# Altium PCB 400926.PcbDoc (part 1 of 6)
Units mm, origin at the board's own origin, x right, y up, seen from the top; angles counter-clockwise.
Board outline 148.5 x 63.5 mm, 4 copper layers (Top Layer, Mid-Layer 1, Mid-Layer 2, Bottom Layer), stack 1.514 mm thick; 311 components, 281 nets, 1495 pads, 2232 vias.
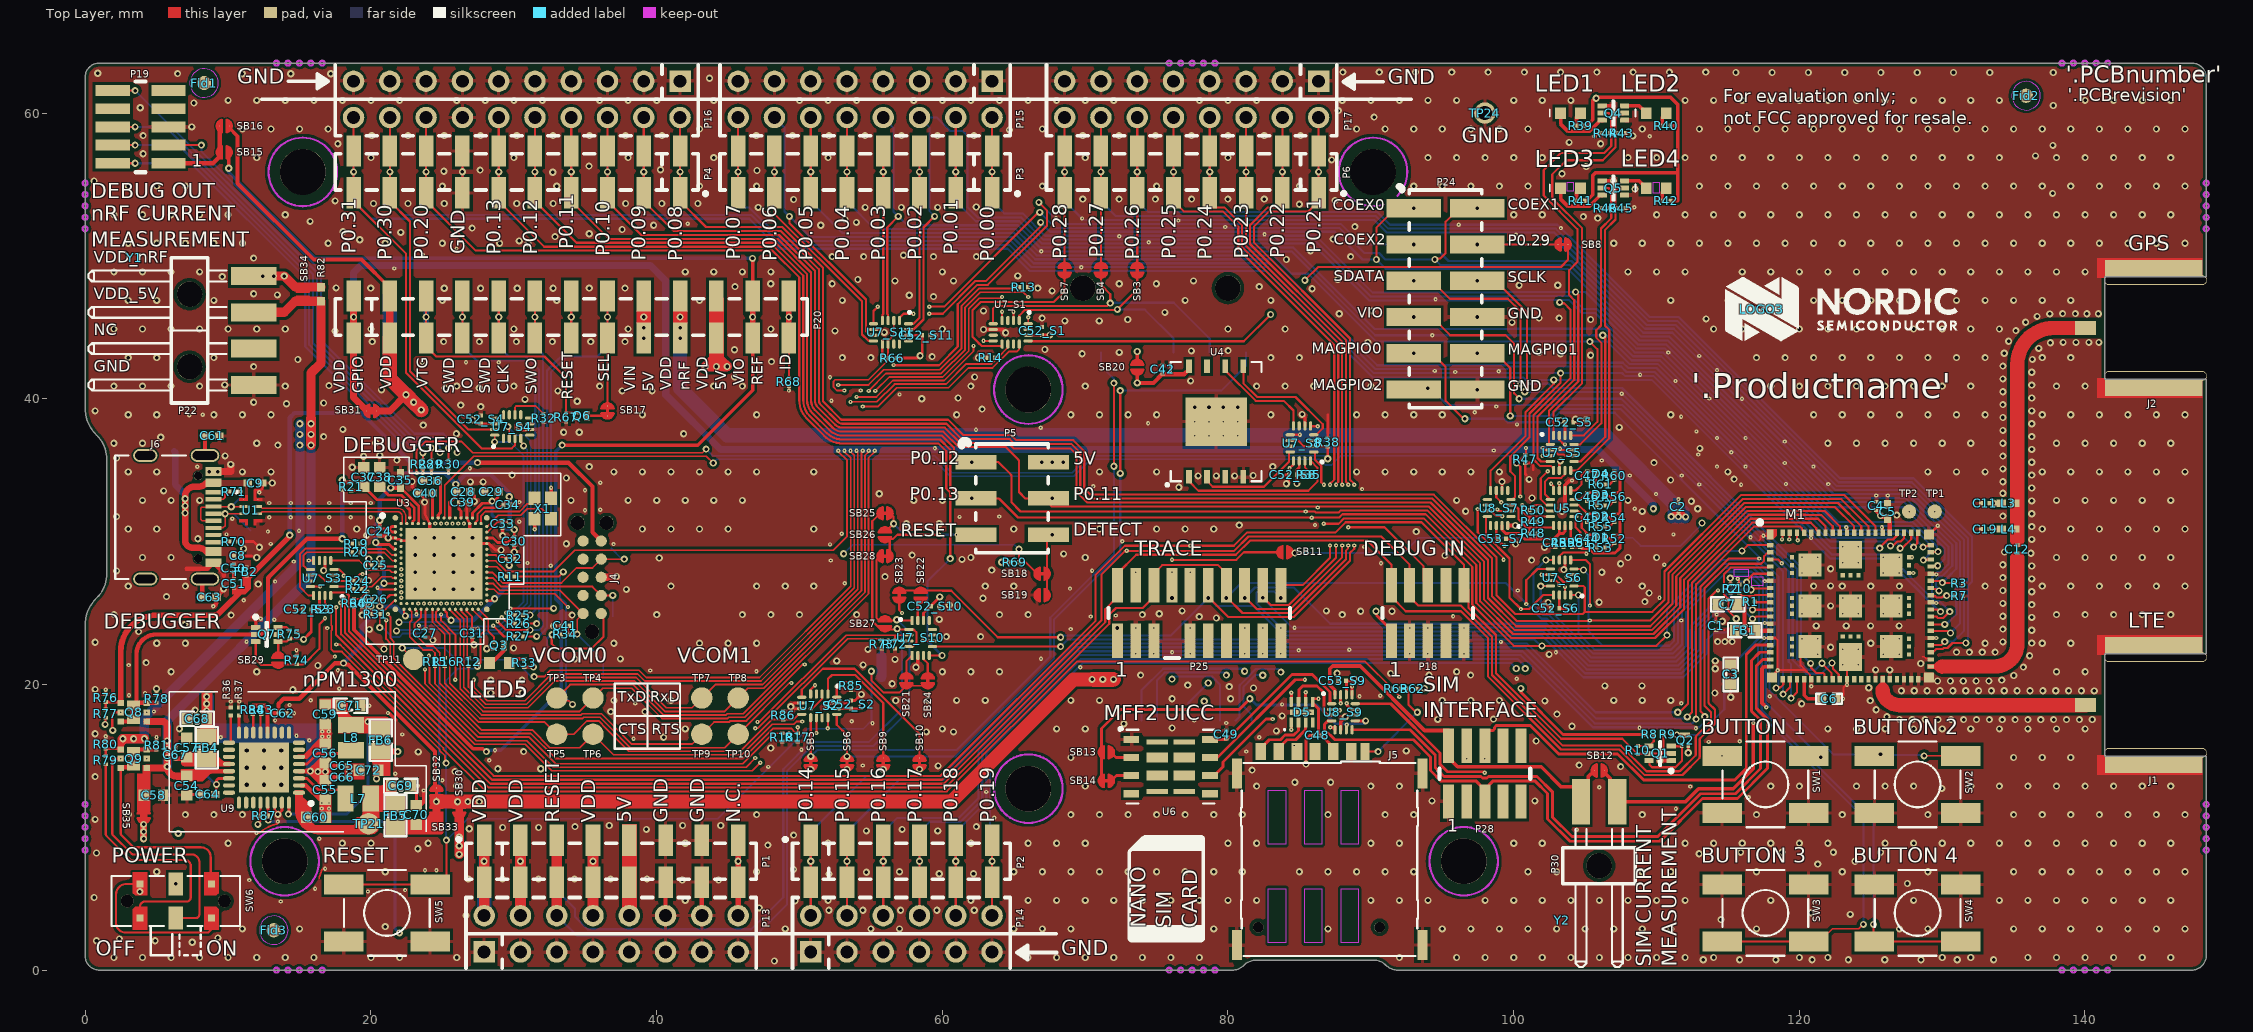
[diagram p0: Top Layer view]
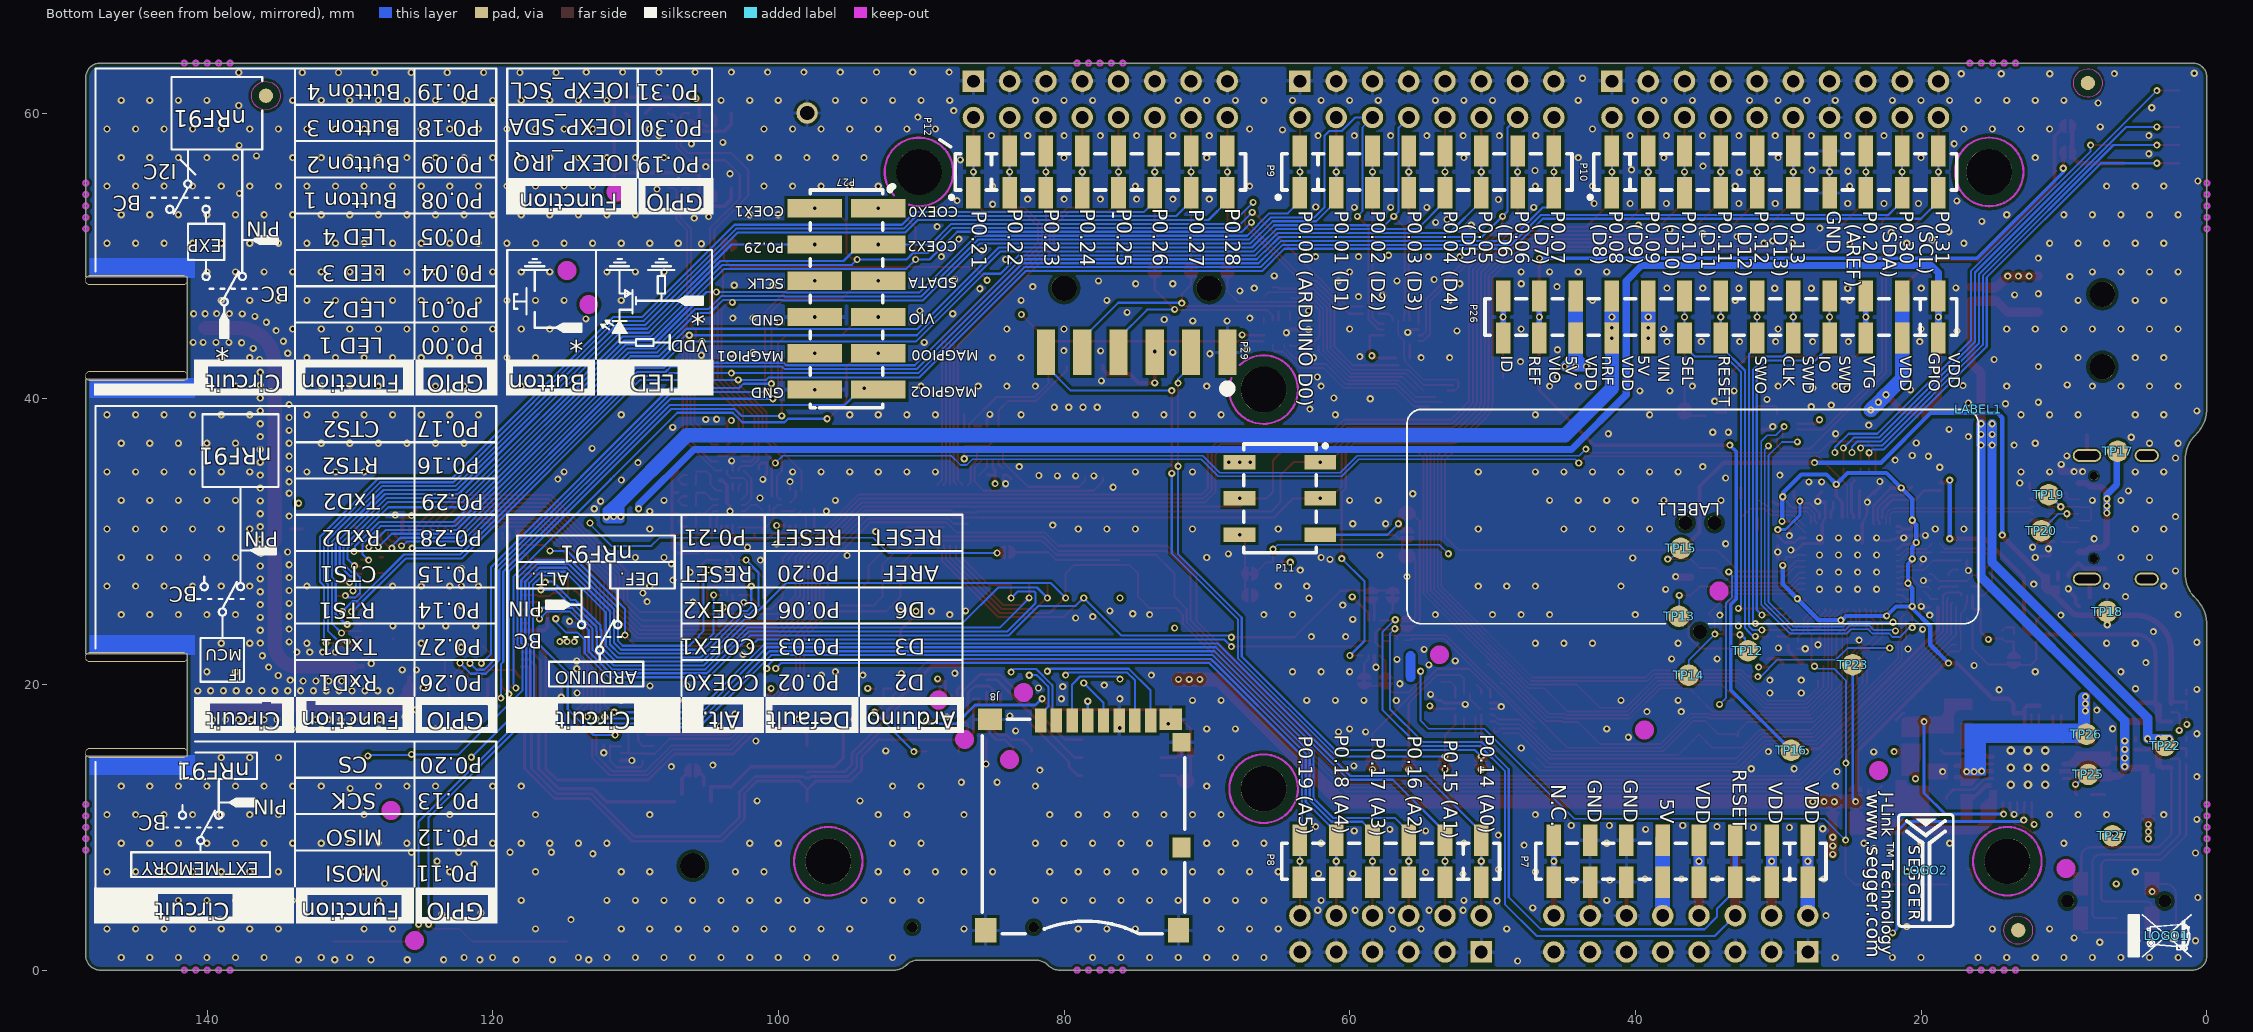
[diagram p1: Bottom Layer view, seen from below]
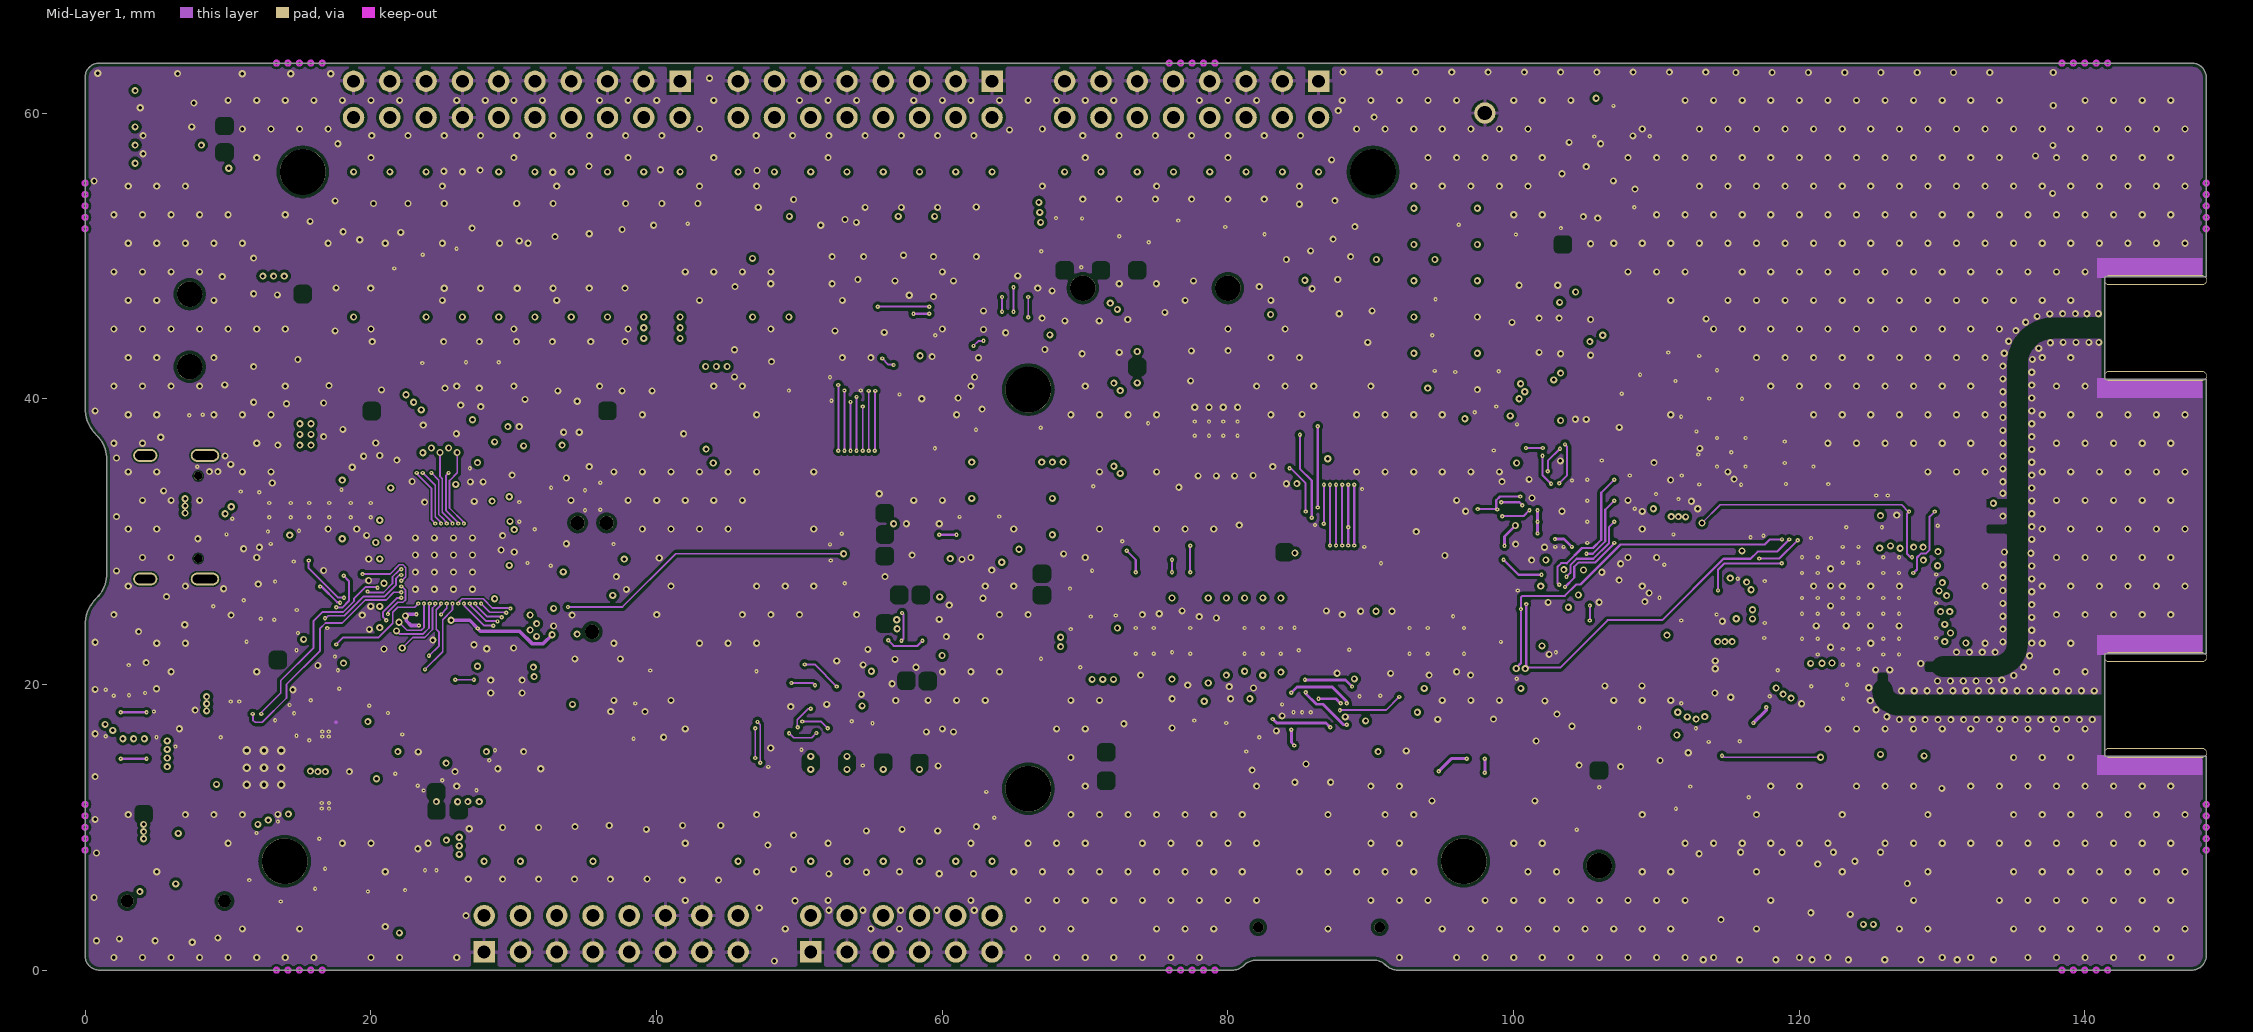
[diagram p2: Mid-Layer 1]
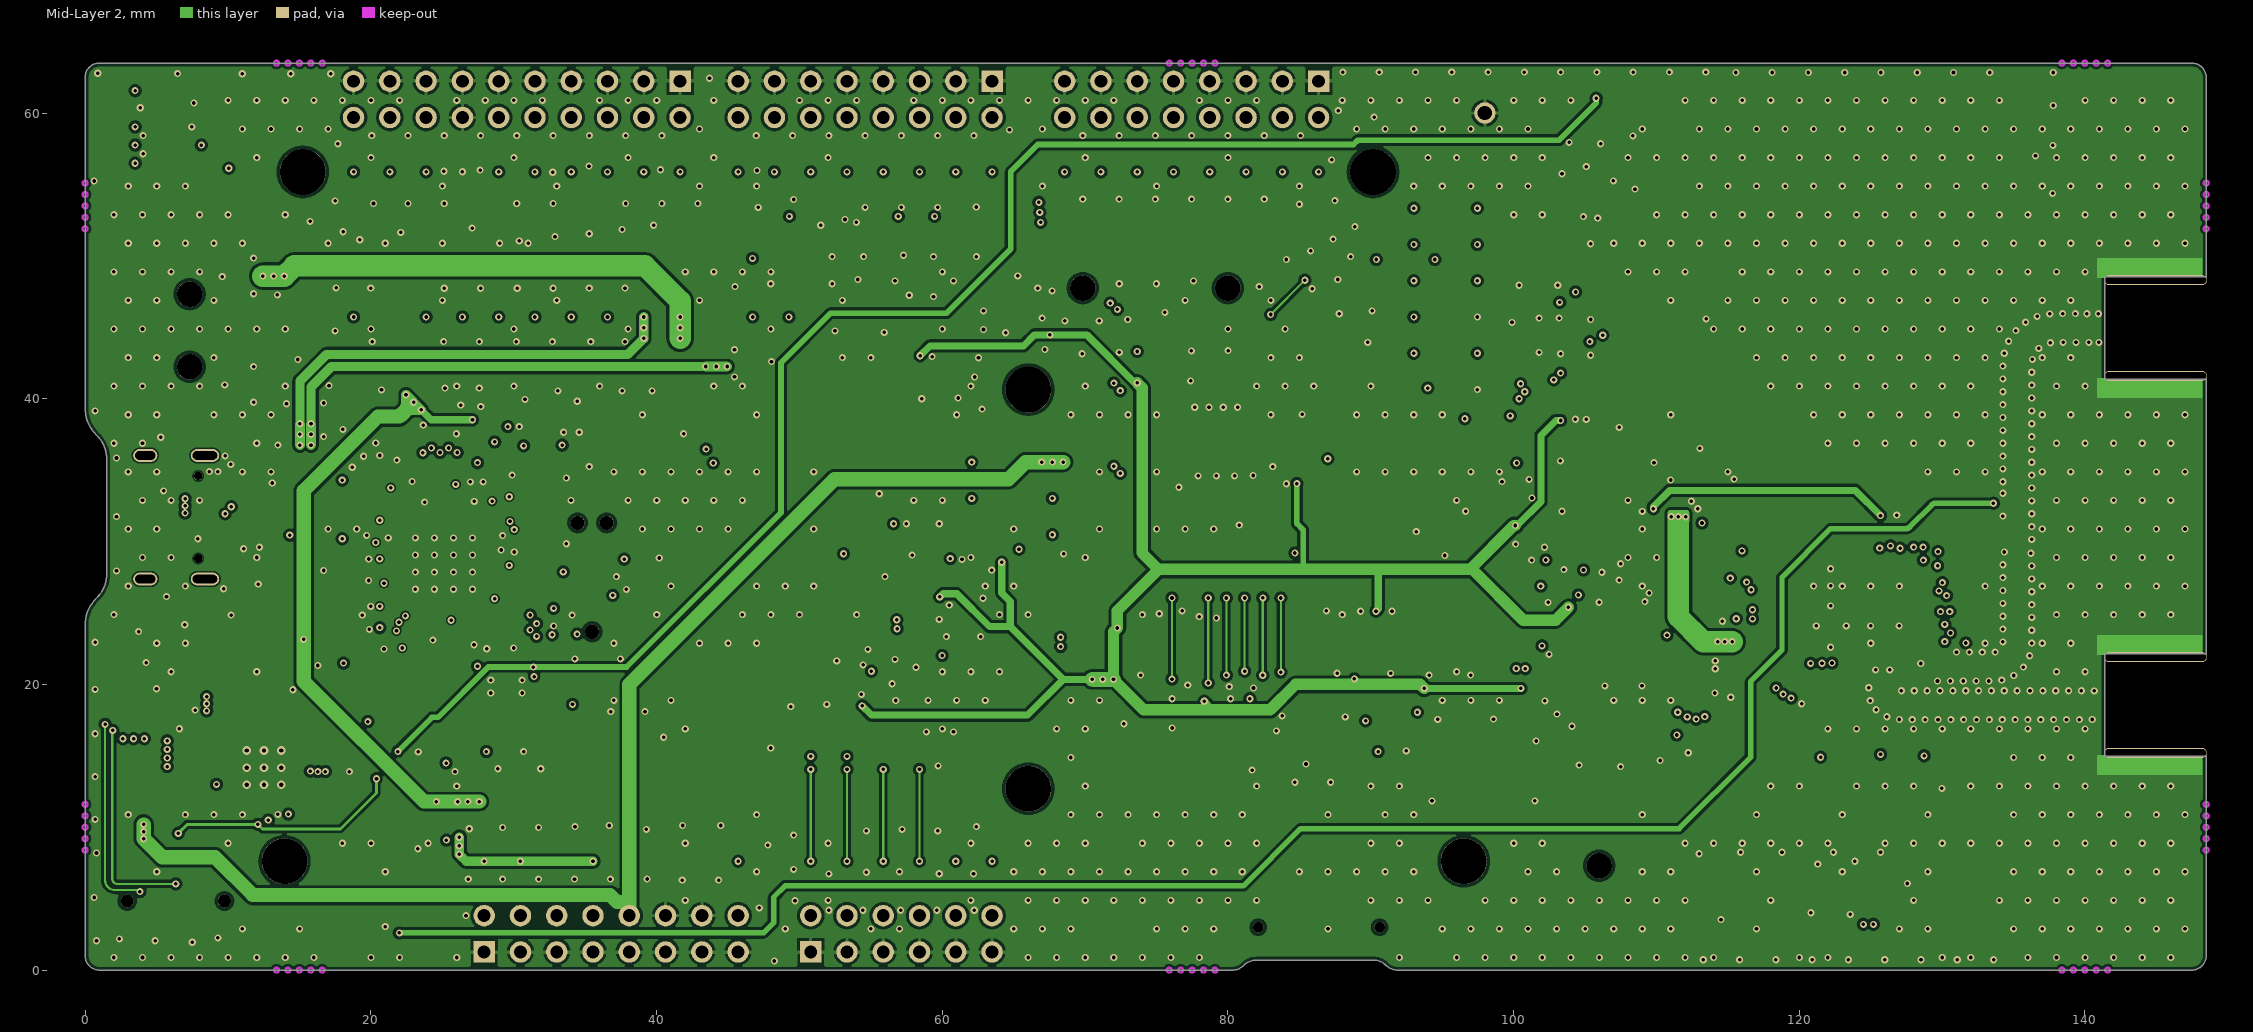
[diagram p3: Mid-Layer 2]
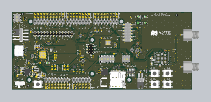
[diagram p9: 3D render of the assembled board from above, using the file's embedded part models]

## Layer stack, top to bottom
Top Solder: solder mask 0.05, Solder Resist Halogen-Free, Dk 3.5
Top Layer: signal copper 0.035
Dielectric1: prepreg 0.072, FR-4 Halogen-Free, Dk 4.18
Mid-Layer 1: signal copper 0.035
Dielectric2: core 1.23, FR-4 Halogen-Free, Dk 4.74
Mid-Layer 2: signal copper 0.035
Dielectric3: prepreg 0.072, FR-4 Halogen-Free, Dk 4.18
Bottom Layer: signal copper 0.035
Bottom Solder: solder mask 0.05, Solder Resist Halogen-Free, Dk 3.5

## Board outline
1,-0.001 cw(c1,0.999) 0,0.999 0,24.12 cw(c2.716,24.12) 0.796,26.041 0.962,26.207 ccw(c-0.876,27.75) 1.524,27.75 1.524,35.75 ccw(c-0.876,35.75) 0.962,37.293 0.796,37.459 cw(c2.716,39.38) 0,39.38 0,62.499 cw(c1,62.499) 1,63.499 147.5,63.499 cw(c147.5,62.499) 148.5,62.499 148.5,48.549 141.4,48.549 141.4,41.349 148.5,41.349 148.5,22.156 141.4,22.156 141.4,14.956 148.5,14.956 148.5,0.999 cw(c147.5,0.999) 147.5,-0.001 91.9,-0.001 cw(c91.9,1.179) 91.066,0.345 ccw(c90.231,-0.49) 90.231,0.69 81.969,0.69 ccw(c81.969,-0.49) 81.134,0.345 cw(c80.3,1.179) 80.3,-0.001

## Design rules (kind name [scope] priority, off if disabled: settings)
BoardOutlineClearance BoardOutlineClearance_SMA [HasFootprint('CONSMA024-G')] p1: gap=0 ignorepadtopadclearanceinfootprint=FALSE
BoardOutlineClearance [OnLayer('Top Layer') or OnLayer('Bottom Layer') or OnLayer('Mid-Layer 1') or OnLayer('Mid-Layer 2')] p2: gap=0.244 ignorepadtopadclearanceinfootprint=FALSE
Clearance SMA [HasFootprint('CONSMA024-G')] p1: gap=0 ignorepadtopadclearanceinfootprint=FALSE
Clearance USB_C [InComponent('J6')] p2: gap=0.1 ignorepadtopadclearanceinfootprint=FALSE
Clearance IMCU_room [WithinRoom('IMCU')] p3: gap=0.1 ignorepadtopadclearanceinfootprint=FALSE
Clearance USB_Poly_Clearance [(InNamedPolygon('Top_Layer-GND')) vs (IsTrack or IsArc) and (InDifferentialPair('D') or InDifferentialPair('USB0'))] p4 off: gap=1 ignorepadtopadclearanceinfootprint=FALSE
Clearance "NPTH clearance" [Not PadIsPlated And HoleSize > 0] p5: gap=0.23 ignorepadtopadclearanceinfootprint=FALSE
Clearance SB_Clearance [HasFootprint('Solderbridge') or HasFootprint('QFN40P180X140X55-10N')] p6: gap=0.127 ignorepadtopadclearanceinfootprint=FALSE except(0: Arc-Hole Track-Hole SMDPad-Hole THPad-Hole Via-Hole Fill-Hole Poly-Hole Region-Hole Text-Hole)
Clearance CSP_Clearance [HasFootprint('BGA4C40P2X2_76X76X62')] p7: gap=0.127 ignorepadtopadclearanceinfootprint=FALSE except(0: Arc-Hole Track-Hole SMDPad-Hole THPad-Hole Via-Hole Fill-Hole Poly-Hole Region-Hole Text-Hole)
Clearance P23_Clearance [HasFootprint('FPC_05P-0.5mm-RA-SMD')] p8: gap=0.127 ignorepadtopadclearanceinfootprint=FALSE except(0: Arc-Hole Track-Hole SMDPad-Hole THPad-Hole Via-Hole Fill-Hole Poly-Hole Region-Hole Text-Hole)
Clearance PSON35P100X50-8N_Clearance [HasFootprint('PSON35P100X50-8N')] p9: gap=0.15 ignorepadtopadclearanceinfootprint=FALSE except(0: Arc-Hole Track-Hole SMDPad-Hole THPad-Hole Via-Hole Fill-Hole Poly-Hole Region-Hole Text-Hole)
Clearance "Net tie_clearance" [InComponent('NT*') vs IsPad] p10: gap=0.001 ignorepadtopadclearanceinfootprint=TRUE
Clearance Polygon_Clearance [InNamedPolygon('Top_Layer-GND') or InNamedPolygon('Bottom_Layer-GND') or InNamedPolygon('Mid_Layer_1-GND') or InNamedPolygon('Mid_Layer_2-GND')] p11: gap=0.2 ignorepadtopadclearanceinfootprint=FALSE
Clearance Top_layer_Clearance [All vs OnLayer('Top Layer')] p12: gap=0.125 ignorepadtopadclearanceinfootprint=FALSE
Clearance USB_Clearance [InDifferentialPairClass('All Differential Pairs')] p13: gap=0.15 ignorepadtopadclearanceinfootprint=FALSE
Clearance RF_Clerance [InNet('RF') or InNet('ANT')] p14: gap=0.203 ignorepadtopadclearanceinfootprint=FALSE except(0: Arc-Hole Track-Hole SMDPad-Hole THPad-Hole Via-Hole Fill-Hole Poly-Hole Region-Hole Text-Hole)
Clearance [All] p15: gap=0.125 ignorepadtopadclearanceinfootprint=FALSE except(0: Poly-Region Region-Region)
ComponentClearance [All] p1 off: gap=0.254 collisioncheckmode=3 verticalgap=0.254 showdistances=FALSE
DiffPairsRouting [InDifferentialPairClass('All Differential Pairs')] p1: maxlimit=0.15 minlimit=0.127 mostfreqgap=0.15 toplayer_mingap=0.15 toplayer_minwidth=0.1 toplayer_maxwidth=0.1 toplayer_prefwidth=0.1 midlayer1_maxgap=0.127 midlayer1_prefgap=0.127 midlayer1_minwidth=0.054 midlayer1_maxwidth=0.054 midlayer1_prefwidth=0.054 midlayer2_maxgap=0.127 midlayer2_prefgap=0.127 midlayer2_minwidth=0.054 midlayer2_maxwidth=0.054 midlayer2_prefwidth=0.054 bottomlayer_mingap=0.15 bottomlayer_minwidth=0.1 bottomlayer_maxwidth=0.1 bottomlayer_prefwidth=0.1 impedanceprofiledriven=TRUE impedanceprofileid={5F1D737F-A6A0-4321-8E3C-81C77A155CAF} impedanceprofilevalue=90.000000 maxuncoupledlength=12.7
FabricationTestPointUsage TestPointUsage [All] p1: valid=0 allowmultiple=FALSE
FabricationTestpoint Testpoint [All] p1: side=3 testpointundercomponent=TRUE minsize=1.016 maxsize=2.54 preferedsize=1.524 minholesize=0 maxholesize=1.016 preferedholesize=0.813 testpointgrid=0.025 allowsidetop=TRUE allowsidebottom=TRUE usegrid=TRUE gridtolerance=0
Height [All] p1 off: minheight=0 maxheight=25.4 prefheight=12.7
HoleSize [All] p1: absolutevalues=TRUE maxlimit=10 minlimit=0.1 maxpercent=80.000 minpercent=20.000
HoleToHoleClearance [All] p1: gap=0.25 allowstackedmicrovias=FALSE
MaxMinImpedance [InNetClass('USB')] p1: minimum=81.00 maximum=99.00
MinimumAnnularRing [All] p1 off: minimumring=0.152
MinimumSolderMaskSliver USB-C [HasFootprint('SD-80259-001')] p1: minsoldermaskwidth=0
MinimumSolderMaskSliver PMIC [WithinRoom('nPM1300')] p2: minsoldermaskwidth=0
MinimumSolderMaskSliver [All] p3: minsoldermaskwidth=0.05
NetAntennae NetAntennae_ANT [InNet('ANT')] p1: netantennaetolerance=40
NetAntennae [All] p2: netantennaetolerance=0
PlaneClearance [All] p1: clearance=0.25
PlaneConnect [All] p1: planeconnectstyle=Direct reliefexpansion=0.508 reliefentries=4 reliefconductorwidth=0.254 reliefairgap=0.254
PolygonConnect VDD_nRF [InNet('VDD_nRF')] p1: connectstyle=Direct reliefconductorwidth=0.254 reliefentries=4 polygonreliefangle="90 Angle" airgapwidth=0.254
PolygonConnect VCC_and_VDD [InNet('NetC50_2') or InNet('NetC8_2') or InNet('NetC70_2') or InNet('VDD')] p2: connectstyle=Direct reliefconductorwidth=0.254 reliefentries=4 polygonreliefangle="90 Angle" airgapwidth=0.254
PolygonConnect GND_Poly [isVia and innet(gnd) or isVia and innet('VDD') or HasFootprint('COAXIAL-SWF') or isVia and innet('VDD_SAM') or InComponent('R80') or HasFootprint('COAXIAL RF U.FL-R-SMT-1') or HasFootprint('DSGP.1575.18') or HasFootprint('DX07S016JA1R1500') or InComponent('C65')or InComponent('C66')or InComponent('C72')] p3: connectstyle=Direct reliefconductorwidth=0.254 reliefentries=4 polygonreliefangle="90 Angle" airgapwidth=0.254
PolygonConnect General [All] p4: connectstyle=Relief reliefconductorwidth=0.25 reliefentries=4 polygonreliefangle="90 Angle" airgapwidth=0.2
RoomDefinition IMCU [InComponentClass('IMCU') vs False] p1: confinementstyle=ConfineIn formatcopy=TRUE lockcomponents=FALSE outline 18.088,33.042 18.088,34.655 18.67,34.655 18.67,36.018 21.455,36.018 21.455,35.513 22.755,35.513 22.755,34.943 25.405,34.943 25.405,34.163 27.705,34.163 29.68,34.163 29.68,33.843 33.38,33.843 33.38,30.782 30.586,30.782 30.586,29.226 30.581,29.226 30.581,28.246 28.954,28.246 28.954,24.429 27.636,24.429 27.636,22.776 24.279,22.776 24.279,20.47 21.721,20.47 21.721,24.429 20.321,24.429 20.321,25.421 19.543,25.421 19.543,27.797 19.543,33.008 18.67,33.008 18.67,33.042
RoomDefinition nPM1300 [InComponentClass('nPM1300') vs False] p2: confinementstyle=ConfineIn formatcopy=TRUE lockcomponents=FALSE outline 5.35,8.144 5.35,10.652 5.818,10.652 5.818,15.86 6.348,15.86 6.348,17.025 6.398,17.025 6.398,18.375 9.691,18.375 9.691,18.878 10.26,18.878 10.26,18.885 16.048,18.885 16.048,19.362 17.248,19.362 17.248,19.375 19.114,19.375 19.114,39.996 21.021,39.996 21.021,22.633 26.049,22.633 26.049,12.151 27.049,12.151 27.049,10.244 23.973,10.244 23.973,9.419 22.781,9.419 22.781,9.117 20.381,9.117 20.381,8.542 7.858,8.542 7.858,8.144
RoutingLayers RoutingLayers_1 [IsMicroVia] p1: top layer_v5=TRUE mid layer 1_v5=TRUE mid layer 2_v5=FALSE bottom layer_v5=FALSE
RoutingLayers [All] p2: top layer_v5=TRUE mid layer 1_v5=TRUE mid layer 2_v5=TRUE bottom layer_v5=TRUE
RoutingVias [All] p1: holewidth=0.25 width=0.5 viastyle="Through Hole" minholewidth=0.1 minwidth=0.3 maxholewidth=0.305 maxwidth=0.61
ShortCircuit "PVSS and GND" [InNet('PVSS1') or InNet('PVSS2') vs InNet('GND')] p1: allowed=TRUE
ShortCircuit ShortCircuit_1 [HasFootprint('P822601')] p2: allowed=TRUE
ShortCircuit [All] p3: allowed=FALSE
SilkToSilkClearance [All] p1: silktosilkclearance=0.15
SilkToSolderMaskClearance SilkscreenOverComponentPads [IsPad] p1: minsilkscreentomaskgap=0.254 clearancetoexposedcopper=TRUE
SolderMaskExpansion SolderMaskExpansion_Via [IsVia] p1: expansion=0.102 istentingtop=TRUE
SolderMaskExpansion SolderMaskExpansion_USB [HasFootprint('L-KLS1-5473')] p2: expansion=0.06 istentingtop=FALSE
SolderMaskExpansion [All] p3: expansion=0.076 istentingtop=FALSE
SupplyNets "Schematic Supply Nets_19" [InNet('VDD_1V8')] p1: voltage=0.000
SupplyNets "Schematic Supply Nets_18" [InNet('VBUSOUT')] p2: voltage=0.000
SupplyNets "Schematic Supply Nets_17" [InNet('VDD')] p3: voltage=0.000
SupplyNets "Schematic Supply Nets_16" [InNet('VBUS')] p4: voltage=0.000
SupplyNets "Schematic Supply Nets_15" [InNet('VIN')] p5: voltage=0.000
SupplyNets "Schematic Supply Nets_14" [InNet('GND')] p6: voltage=0.000
SupplyNets "Schematic Supply Nets_13" [InNet('VIOEXT')] p7: voltage=0.000
SupplyNets "Schematic Supply Nets_12" [InNet('5V')] p8: voltage=0.000
SupplyNets "Schematic Supply Nets_11" [InNet('VIO_REF')] p9: voltage=0.000
SupplyNets "Schematic Supply Nets_10" [InNet('VIN_5V')] p10: voltage=0.000
SupplyNets "Schematic Supply Nets_9" [InNet('VDD_IMCU')] p11: voltage=0.000
SupplyNets "Schematic Supply Nets_8" [InNet('VIO')] p12: voltage=0.000
SupplyNets "Schematic Supply Nets_7" [InNet('VDD_3V0')] p13: voltage=0.000
SupplyNets "Schematic Supply Nets_6" [InNet('VIN:5V')] p14: voltage=0.000
SupplyNets "Schematic Supply Nets_5" [InNet('FB2:VBUS')] p15: voltage=0.000
SupplyNets "Schematic Supply Nets_4" [InNet('VDD_nRF')] p16: voltage=0.000
SupplyNets "Schematic Supply Nets_3" [InNet('VDD_GNSS')] p17: voltage=0.000
SupplyNets "Schematic Supply Nets_2" [InNet('VDD_5V')] p18: voltage=0.000
SupplyNets "Schematic Supply Nets_1" [InNet('VSYS')] p19: voltage=0.000
SupplyNets "Schematic Supply Nets" [InNet('VDD_GPIO')] p20: voltage=0.000
UnpouredPolygon [All] p1 off:
Width Width_RF [InNet('ANT') or InNet('LTE_RF1') or InNet('GPS_RF1')] p1: maxlimit=1.008 minlimit=0.1 preferedwidth=1.008 toplayer_minwidth=1 bottomlayer_minwidth=1 impedanceprofiledriven=TRUE impedanceprofileid={28F3A609-7DB3-45B1-BB45-39A827C1017D} impedanceprofilevalue=50.000000 minimp=50.000000 maximp=50.000000 favimp=50.000000
Width Width_Diff [(InDifferentialPairClass('All Differential Pairs'))] p2: maxlimit=0.165 minlimit=0.1 preferedwidth=0.165 toplayer_maxwidth=0.1 toplayer_prefwidth=0.1 bottomlayer_maxwidth=0.1 bottomlayer_prefwidth=0.1 minimp=50.000000 maximp=50.000000 favimp=50.000000
Width Width_GPIO [InNetClass('GPIO')] p3: maxlimit=0.152 minlimit=0.125 preferedwidth=0.15 minimp=50.000000 maximp=50.000000 favimp=50.000000
Width Width_GPIO_1 [InNetClass('COEX')] p4: maxlimit=0.152 minlimit=0.125 preferedwidth=0.15 minimp=50.000000 maximp=50.000000 favimp=50.000000
Width Width_GPIO_2 [InNetClass('SWD')] p5: maxlimit=0.152 minlimit=0.125 preferedwidth=0.15 minimp=50.000000 maximp=50.000000 favimp=50.000000
Width Width_GPIO_3 [InNetClass('UART')] p6: maxlimit=0.152 minlimit=0.125 preferedwidth=0.15 minimp=50.000000 maximp=50.000000 favimp=50.000000
Width [All] p7: maxlimit=2.54 minlimit=0.125 preferedwidth=0.15
14 further rules are at their usual default settings.

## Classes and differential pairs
channel class pca10201_switch_nx: S7 S9
channel class pca10201_switch_fsa: S1 S2 S3 S4 S5 S6 S8 S10 S11
differential pair class IMCU: D
differential pair class D:J6: D:J6
net class USB: D:J6_N D:J6_P D_N D_P
net class VCOM: VCOM0_CTRL VCOM0_CTS VCOM0_HWFC VCOM0_RTS VCOM0_RXD VCOM0_TXD VCOM1_CTRL VCOM1_CTS VCOM1_HWFC VCOM1_RTS VCOM1_RXD VCOM1_TXD
net class nRF9151_UART: P0.14/AIN1 P0.15/AIN2 P0.16/AIN3 P0.17/AIN4 P0.26 P0.27 P0.28 P0.29
net class EXT_MEM: P0.11 P0.12 P0.13/AIN0 P0.20/AIN7
component class IMCU: C24 C25 C26 C27 C28 C29 C30 C31 C32 C33 C34 C35 C36 C37 C38 C39 C40 R21 TP11 U3 X1
component class nPM1300: C54 C55 C56 C57 C59 C60 C62 C64 C65 C66 C67 C68 C69 C70 C71 C72 FB4 FB5 FB6 L7 L8 R36 R37 R87 SB30 SB31 SB32 SB33 TP21 TP23 TP25 TP26 TP27 U9
net class RF: GPS_RF1 GPS_RF2 LTE_RF1
net class SWD: P0.22 RESET SWD0_CLK SWD0_IO SWD0_RESET SWD0_SEL SWD0_SWO SWD1_CLK SWD1_IO SWD1_RESET SWD1_SEL SWD1_SWO SWD3_CLK SWD3_IO SWD3_RESET SWD3_SWO SWD_CTRL SWDCLK SWDIO
net class COEX: COEX0 COEX1 COEX2 MAGPIO0 MAGPIO1 MAGPIO2 MIPI_SCLK MIPI_SDATA MIPI_VIO
net class GPIO: AREF BTN1_EXT BTN2_EXT BTN3_EXT BTN4_EXT BUTTON1 BUTTON2 BUTTON3 BUTTON4 COEX0 COEX1 COEX2 COEX_SELECT COM.CH1_S1 COM.CH2_S2 COM.CH3_S1 COM.CH4_S2 EXT_MEM_C\S\ EXT_MEM_CTRL EXT_MEM_MISO EXT_MEM_MOSI EXT_MEM_SCK IMCU_LED IMCU_SCL IMCU_SDA INT_EXT IOEXP_CTRL LED1 LED1_EXT LED2 LED2_EXT LED3 LED3_EXT LED4 LED4_EXT MAGPIO0 MAGPIO1 MAGPIO2 MIPI_SCLK MIPI_SDATA MIPI_VIO NC.CH1_S3 NC.CH3_S3 NC.CH4_S3 NetC44_1 NetC45_2 NetC46_2 NetC47_2 NetR51_1 NetR58_1 NO.CH1_S8 P0.00 P0.01 P0.02 P0.03 P0.04 P0.05 P0.06 P0.07 P0.08 P0.09 P0.10 P0.11 P0.12 P0.13/AIN0 P0.14/AIN1 P0.15/AIN2 P0.16/AIN3 P0.17/AIN4 P0.18/AIN5 P0.19/AIN6 P0.20/AIN7 P0.21 P0.22 P0.23 P0.24 P0.25 P0.26 P0.27 P0.28 P0.29 P0.30 P0.31 RESET RESET_BUTTON RESET_IN_CTRL RESET_OUT_CTRL SCL_EXT SDA_EXT SHIELD_DETECT SIM_SELECT SWD0_CLK SWD0_IO SWD0_RESET SWD0_SEL SWD0_SWO SWD1_CLK SWD1_IO SWD1_RESET SWD1_SEL SWD1_SWO SWD3_CLK SWD3_IO SWD3_RESET SWD3_SWO SWD_CTRL SWDCLK SWDIO TGT_SCL TGT_SDA TGT_TWI_CTRL UART1.CTS UART1.RTS UART1.RXD UART1.TXD UART2.CTS UART2.RTS UART2.RXD UART2.TXD USB_DETECT VCOM0_CTRL VCOM0_CTS VCOM0_HWFC VCOM0_RTS VCOM0_RXD VCOM0_TXD VCOM1_CTRL VCOM1_CTS VCOM1_HWFC VCOM1_RTS VCOM1_RXD VCOM1_TXD VIO_REF_SENSE
differential pair D: +D_P -D_N
differential pair D:J6: +D:J6_P -D:J6_N

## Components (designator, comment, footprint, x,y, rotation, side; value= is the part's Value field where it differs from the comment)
C1 "1.0µF" CAPC0603X03L_C 114.19,24.099 r90 top
C2 "1.0µF" CAPC0603X03L_C 111.55,32.424 r90 top
C3 "10µF" CAPC1608X06L 115.2,20.699 r270 top
C4 "100nF" CAPC0603X03L_C 125.4,32.499 r90 top
C5 "4.7µF" CAPC1005X04L 126.2,32.099 r90 top
C6 "4.7µF" CAPC1005X04L 122.1,18.999 r0 top
C7 "10µF" CAPC1608X06L 115,25.599 r180 top
C8 "100nF" CAPC0603X03L_C 10.7,28.999 r180 top
C9 "1.0µF" CAPC1005X04L 11.9,34.099 r180 top
C10 "100nF" CAPC0603X03L_C 115.8,26.699 r90 top
C11 "39pF" CAPC0603X03L_C 133.03,32.679 r0 top
C12 "39pF" CAPC0603X03L_C 135.28,29.479 r270 top
C19 "N.C." CAPC0603X03L_C_NC 133.03,30.879 r0 top
C24 "100nF" CAPC0603X03L_C 20.625,30.708 r90 top
C25 "100nF" CAPC0603X03L_C 20.35,28.333 r0 top
C26 "100nF" CAPC0603X03L_C 20.35,25.958 r180 top
C27 "100nF" CAPC0603X03L_C 23.827,23.583 r90 top
C28 "1.0µF" CAPC1005X04L 26.475,33.483 r0 top
C29 "1.0µF" CAPC1005X04L 28.45,33.483 r0 top
C30 "2.2nF" CAPC0603X03L_C 30.05,30.033 r270 top
C31 "100nF" CAPC0603X03L_C 27.1,23.583 r90 top
C32 "100nF" CAPC0603X03L_C 29.775,28.783 r180 top
C33 "100nF" CAPC0603X03L_C 29.225,31.233 r90 top
C34 "100nF" CAPC0603X03L_C 29.575,32.574 r0 top
C35 "1.0µF" CAPC1005X04L 22.075,34.283 r270 top
C36 "1.0µF" CAPC1005X04L 24.175,34.263 r0 top
C37 "4.7µF" CAPC1608X06L 19.5,34.513 r90 top
C38 "4.7µF" CAPC1608X06L 20.625,34.513 r90 top
C39 "100nF" CAPC0603X03L_C 26.444,32.758 r0 top
C40 "1.0µF" CAPC1005X04L 23.825,33.388 r0 top
C41 "10nF" CAPC0603X03L_C 33.625,24.099 r0 top
C42 "100nF" CAPC0603X03L_C 75.45,42.049 r270 top
C43 "100nF" CAPC0603X03L_C 102.927,29.911 r90 top
C44 "1.0µF" CAPC0603X03L_C 105.174,30.19 r270 top
C45 "1.0µF" CAPC0603X03L_C 105.174,31.663 r90 top
C46 "1.0µF" CAPC0603X03L_C 105.174,33.136 r90 top
C47 "1.0µF" CAPC0603X03L_C 105.174,34.61 r90 top
C48 "10nF" CAPC0603X03L_C 86.275,16.424 r180 top
C49 "N.C." CAPC0603X03L_C_NC 79.9,16.499 r270 top
C50 "10nF" CAPC0603X03L_C 10.425,28.149 r90 top
C51 "100nF" CAPC0603X03L_C 10.425,27.049 r270 top
C52_S1 "100nF" CAPC0603X03L_C 67,44.749 r90 top (schematic designator C52)
C52_S2 "100nF" CAPC0603X03L_C 53.625,18.599 r90 top (schematic designator C52)
C52_S3 "100nF" CAPC0603X03L_C 15.55,25.249 r180 top (schematic designator C52)
C52_S4 "100nF" CAPC0603X03L_C 27.7,38.549 r90 top (schematic designator C52)
C52_S5 "100nF" CAPC0603X03L_C 103.898,38.358 r0 top (schematic designator C52)
C52_S6 "100nF" CAPC0603X03L_C 102.923,25.333 r180 top (schematic designator C52)
C52_S8 "100nF" CAPC0603X03L_C 84.553,34.67 r180 top (schematic designator C52)
C52_S10 "100nF" CAPC0603X03L_C 59.5,25.474 r0 top (schematic designator C52)
C52_S11 "100nF" CAPC0603X03L_C 58.9,44.449 r0 top (schematic designator C52)
C53_S7 "100nF" CAPC0603X03L_C 99.197,30.191 r0 top (schematic designator C53)
C53_S9 "100nF" CAPC0603X03L_C 88,20.249 r180 top (schematic designator C53)
C54 "1.0µF" CAPC1608X06L 7.127,12.921 r90 top
C55 "10µF" CAPC1608X06L 16.827,12.621 r90 top
C56 "10µF" CAPC1608X06L 16.827,15.171 r270 top
C57 "10µF" CAPC1608X06L 7.127,15.571 r270 top
C58 "4.7µF" CAPC1608X06L 4.795,12.242 r180 top
C59 "10µF" CAPC1608X06L 16.827,17.908 r90 top
C60 "10µF" CAPC1608X06L 16.15,10.699 r180 top
C61 "10nF" CAPC1005X04L 8.9,37.399 r0 top
C62 "100nF" CAPC0603X03L_C 13.825,17.974 r0 top
C63 "10nF" CAPC1005X04L 8.7,26.099 r0 top
C64 "1.0µF" CAPC1005X04L 8.6,12.299 r0 top
C65 "1.0nF" CAPC0603X03L_C 18.012,14.296 r180 top
C66 "1.0nF" CAPC0603X03L_C 18.012,13.496 r180 top
C67 "1.0nF" CAPC0603X03L_C 6.327,15.081 r270 top
C68 "N.C." CAPC1608X06L_NC 7.852,17.596 r0 top
C69 "N.C." CAPC1608X06L_NC 22.102,12.896 r180 top
C70 "100nF" CAPC1608X06L 23.194,10.873 r270 top
C71 "N.C." CAPC1608X06L_NC 18.581,18.504 r180 top
C72 "100nF" CAPC1608X06L 19.852,13.996 r0 top
D1 "CFSH05-20L" SODFL35X40-2N 106.114,30.317 r180 top
D2 "CFSH05-20L" SODFL35X40-2N 106.114,31.79 r180 top
D3 "CFSH05-20L" SODFL35X40-2N 106.114,33.263 r180 top
D4 "CFSH05-20L" SODFL35X40-2N 106.114,34.737 r180 top
D5 "TPD3F303DPVR" SON50P210X160X65_HS-9N 85.2,18.049 r90 top
FB1 "22R@100M/6A" INDC1608X06L 116.2,23.799 r0 top
FB2 "120R/0.9A" INDC0603X03L_C 11.3,27.899 r270 top
FB4 "0R" RESC2012X11L 8.527,15.571 r90 top
FB5 "0R" RESC2012X11L 21.727,10.821 r270 top
FB6 "0R" RESC2012X11L 20.7,16.099 r270 top
Fid1 "Fiducial mark" Fiducial 8.335,62.103 r0 top value=N.A.
Fid2 "Fiducial mark" Fiducial 135.89,61.213 r0 top value=N.A.
Fid3 "Fiducial mark" Fiducial 13.208,2.794 r0 top value=N.A.
J1 "SMA Edge" CONSMA024-G 144.95,18.556 r270 top
J2 "SMA Edge" CONSMA024-G 144.95,44.949 r270 top
J4 "TC2050-IDC" TC2050-IDC-NLFP 35.5,27.499 r90 top
J5 "KLS1-SIM-066" KLS1-SIM-066 82.3,15.299 r0 top
J6 "USB-C 2.0" SD-80259-001 6.6,31.704 r270 top
J8 "microSD Card Connector" Molex_502774-0891 72.75,17.549 r0 bottom locked
L3 "68nH" INDC1005X04L_WW 134.63,32.679 r0 top
L4 "N.C." INDC1005X04L_NC 134.63,30.879 r180 top
L7 "2.2µH" INDC2016X10N 19.112,11.996 r180 top
L8 "2.2µH" INDC2016X10N 18.625,16.274 r270 top
LABEL1 "15x40mm" LabelSilk_15x40 16,39.25 r0 bottom
LED1 "L0603G" LED_0603_G 104,59.999 r0 top
LED2 "L0603G" LED_0603_G 110,59.999 r0 top
LED3 "L0603G" LED_0603_G 104,54.749 r0 top
LED4 "L0603G" LED_0603_G 110,54.749 r0 top
LED5 "L0603G" LED_0603_G 29,21.499 r0 top
LOGO1 "WEE Symbol" WEEE_3x4.5mm 2.8,2.4 r270 bottom
LOGO2 "Segger Logo S" SEGGER_LOGO_S 19.675,6.975 r270 bottom
LOGO3 "Nordic Logo" NORDIC_LOGO_LYING 117.4,46.274 r0 top
M1 "nRF9151-LACAA1A" LGA50P1210X1110X130-113N 123.6,25.499 r270 top
P1 "Socket 1x8" SOCKET_1x8_SMD 27.94,7.62 r0 top
P2 "Socket 1x6" SOCKET_1x6_SMD 50.8,7.62 r0 top
P3 "Socket 1x8" SOCKET_1x8_SMD 63.5,55.88 r180 top
P4 "Socket 1x10" SOCKET_1x10_SMD 41.656,55.88 r180 top
P5 "Pin Hdr 2x3" HDR_2x3-SMD 64.897,33.02 r270 top
P6 "Socket 1x8" SOCKET_1x8_SMD 86.36,55.88 r180 top
P7 "Pin List 1x8" LIST_1x8_SMD-NC 27.94,7.62 r0 bottom
P8 "Pin List 1x6" LIST_1x6_SMD-NC 50.8,7.62 r0 bottom
P9 "Pin List 1x8" LIST_1x8_SMD-NC 63.5,55.88 r180 bottom
P10 "Pin List 1x10" LIST_1x10_SMD-NC 41.656,55.88 r180 bottom
P11 "Socket 2x3" SOCKET_2x3_SMD-2.54mm-NC 64.897,33.02 r90 bottom
P12 "Pin List 1x8" LIST_1x8_SMD-NC 86.36,55.88 r180 bottom
P13 "Pin Header 2x8" HDR_2x8-NC 36.83,2.54 r0 top
P14 "Pin Header 2x6" HDR_2x6-NC 57.15,2.54 r0 top
P15 "Pin Header 2x8" HDR_2x8-NC 54.61,60.96 r180 top
P16 "Pin Header 2x10" HDR_2x10-NC 30.226,60.96 r180 top
P17 "Pin Header 2x8" HDR_2x8-NC 77.47,60.96 r180 top
P18 "Pin Header 2x5, 1.27mm" HDR_2x5-SMD-1.27mm-K 94,24.999 r0 top
P19 "Pin Header 2x5, 1.27mm" HDR_2x5-SMD-1.27mm-K 3.886,59.03 r90 top
P20 "Pin List 1x13" LIST_1x13_SMD 18.796,45.72 r0 top
P22 "Pin List 1x4, Angled" LIST_ANG_1x4-SMD-2.54MM 11.811,44.778 r270 top
P24 "Socket 2x6" SOCKET_2x6_SMD-2.54mm#1 95.25,46.99 r270 top
P25 "Pin Header 2x10, 1.27mm, SWD" HDR_2x10-SMD-1.27mm-K-SWD 78,24.999 r0 top
P26 "Socket 1x13" LIST_1x13_SMD-NC 18.796,45.72 r0 bottom
P27 "Socket 2x6" SOCKET_2x6_SMD-2.54mm#2 95.25,46.99 r270 bottom
P28 "Pin Header 2x5, 1.27mm" HDR_2x5-SMD-1.27mm 98,13.749 r0 top
P29 "Pin List 1x6, Angled" LIST_ANG_1x6-SMD-2.54MM 74.93,43.249 r0 bottom
P30 "Pin List 1x2, Angled" LIST_ANG_1x2-SMD-2.54MM 106,11.799 r0 top
Q1 "DMC2400UV" SOTFL50P162X60-6N 110.265,15.174 r180 top
Q2 "RV2C010UNT2L" DFN65P100X40-3L 112.015,16.099 r90 top
Q3 "RV2C010UNT2L" DFN65P100X40-3L 28.975,22.724 r0 top
Q4 "UM6X1NA" SOTFL50P162X60-6N 107,59.999 r180 top
Q5 "UM6X1NA" SOTFL50P162X60-6N 107,54.749 r180 top
Q6 "RV2C010UNT2L" DFN65P100X40-3L 34.775,38.799 r0 top
Q7 "DMC2400UV" SOTFL50P162X60-6N 12.725,23.499 r0 top
Q8 "MCM2301-TP" DFN65P200X200X80_HS-6N 3.4,18.049 r0 top
Q9 "MCM2301-TP" DFN65P200X200X80_HS-6N 3.4,14.799 r0 top
R1 "10k" RESC0603X03L_C 116.6,25.799 r0 top
R2 "1k" RESC0603X03L_C 115.2,26.699 r270 top
R3 "1M0" RESC0603X03L_C 131.2,27.099 r180 top
R7 "1M0" RESC0603X03L_C 131.2,26.199 r180 top
R8 "10k" RESC0603X03L_C 109.54,16.499 r0 top
R9 "N.C." RESC0603X03L_C_NC 110.815,16.499 r0 top
R10 "100k" RESC0603X03L_C 108.715,15.399 r90 top
R11 "150R" RESC0603X03L_C 29.775,27.549 r0 top
R12 "150R" RESC0603X03L_C 26.85,21.583 r270 top
R13 "1M0" RESC0603X03L_C 65.725,47.799 r0 top
R14 "1M0" RESC0603X03L_C 63.4,42.874 r0 top
R15 "150R" RESC0603X03L_C 24.5,21.583 r270 top
R16 "150R" RESC0603X03L_C 25.175,21.583 r270 top
R17 "1M0" RESC0603X03L_C 49.9,16.299 r270 top
R18 "1M0" RESC0603X03L_C 48.8,16.299 r90 top
R19 "150R" RESC0603X03L_C 18.975,29.858 r180 top
R20 "150R" RESC0603X03L_C 18.975,29.258 r180 top
R21 "2R2" RESC0603X03L_C 18.625,33.849 r270 top
R22 "150R" RESC0603X03L_C 19.075,26.683 r180 top
R23 "N.C." RESC0603X03L_C_NC 16.675,25.249 r180 top
R24 "1M0" RESC0603X03L_C 19.075,27.274 r180 top
R25 "150R" RESC0603X03L_C 30.375,24.858 r0 top
R26 "150R" RESC0603X03L_C 30.375,24.258 r0 top
R27 "150R" RESC0603X03L_C 30.375,23.358 r0 top
R28 "150R" RESC0603X03L_C 23.65,35.408 r90 top
R29 "150R" RESC0603X03L_C 24.25,35.408 r90 top
R30 "150R" RESC0603X03L_C 25.45,35.408 r90 top
R31 "1M0" RESC0603X03L_C 20.35,24.924 r180 top
R32 "1M0" RESC0603X03L_C 32.1,38.649 r90 top
R33 "120R" RESC0603X03L_C 30.75,21.499 r270 top
R34 "100k" RESC0603X03L_C 33.625,23.499 r180 top
R35 "100k" RESC0603X03L_C 85.653,34.67 r180 top
R36 "47k" RESC0603X03L_C 10.2,18.099 r90 top
R37 "150k" RESC0603X03L_C 10.769,18.106 r90 top
R38 "1M0" RESC0603X03L_C 87.003,36.945 r270 top
R39 "120R" RESC0603X03L_C 104.698,59.117 r0 top
R40 "120R" RESC0603X03L_C 110.698,59.117 r0 top
R41 "120R" RESC0603X03L_C 104.698,53.867 r0 top
R42 "120R" RESC0603X03L_C 110.698,53.867 r0 top
R43 "1M0" RESC0603X03L_C 107.574,58.599 r180 top
R44 "1M0" RESC0603X03L_C 106.456,58.599 r0 top
R45 "1M0" RESC0603X03L_C 107.563,53.349 r180 top
R46 "1M0" RESC0603X03L_C 106.445,53.349 r0 top
R47 "1M0" RESC0603X03L_C 100.825,35.774 r90 top
R48 "4k7" RESC0603X03L_C 101.403,30.571 r0 top
R49 "4k7" RESC0603X03L_C 101.403,31.384 r0 top
R50 "12k" RESC0603X03L_C 101.403,32.197 r0 top
R51 "12k" RESC0603X03L_C 104.68,29.911 r270 top
R52 "100k" RESC0603X03L_C 107.048,30.19 r90 top
R53 "18k" RESC0603X03L_C 106.114,29.58 r0 top
R54 "100k" RESC0603X03L_C 107.048,31.663 r90 top
R55 "18k" RESC0603X03L_C 106.114,31.054 r0 top
R56 "100k" RESC0603X03L_C 107.048,33.136 r90 top
R57 "18k" RESC0603X03L_C 106.114,32.527 r0 top
R58 "0R" RESC0603X03L_C 104.095,29.911 r270 top
R59 "N.C." RESC0603X03L_C_NC 103.511,29.911 r90 top
R60 "100k" RESC0603X03L_C 107.048,34.61 r90 top
R61 "18k" RESC0603X03L_C 106.114,34 r0 top
R62 "1M0" RESC0603X03L_C 92.95,19.699 r180 top
R63 "100k" RESC0603X03L_C 91.8,19.699 r0 top
R64 "100k" RESC0603X03L_C 18.825,25.699 r90 top
R65 "100k" RESC0603X03L_C 19.4,25.699 r90 top
R66 "1M0" RESC0603X03L_C 56.5,42.849 r180 top
R67 "1M0" RESC0603X03L_C 33.675,38.699 r270 top
R68 "1k87" RESC0603X03L_C 49.276,41.174 r90 top
R69 "1M0" RESC0603X03L_C 65.1,28.549 r180 top
R70 "5k1" RESC0603X03L_C 10.4,29.999 r180 top
R71 "5k1" RESC0603X03L_C 10.4,33.499 r180 top
R72 "1M0" RESC0603X03L_C 56.7,22.799 r270 top
R73 "1M0" RESC0603X03L_C 55.775,22.799 r90 top
R74 "47k" RESC0603X03L_C 14.825,21.699 r270 top
R75 "1M0" RESC0603X03L_C 14.325,23.499 r90 top
R76 "100k" RESC0603X03L_C 1.45,19.049 r90 top
R77 "10k" RESC0603X03L_C 1.45,17.949 r270 top
R78 "150k" RESC0603X03L_C 5,18.999 r270 top
R79 "10k" RESC0603X03L_C 1.45,14.699 r90 top
R80 "1M0" RESC0603X03L_C 1.45,15.799 r90 top
R81 "100k" RESC0603X03L_C 5,15.734 r90 top
R82 "N.C." RESC1005X04L_NC 16.51,47.318 r270 top
R83 "4k7" RESC0603X03L_C 12.337,18.216 r90 top
R84 "4k7" RESC0603X03L_C 11.737,18.216 r90 top
R85 "100k" RESC0603X03L_C 53.625,19.899 r270 top
R86 "100k" RESC0603X03L_C 48.875,17.824 r90 top
R87 "0R" RESC0603X03L_C 12.537,10.799 r0 top
SB3 "Solderbridge" Solderbridge_Shorted 73.66,48.999 r270 top net-tie
SB4 "Solderbridge" Solderbridge_Shorted 71.12,48.999 r270 top net-tie
SB5 "Solderbridge" Solderbridge_Shorted 50.8,14.499 r90 top net-tie
SB6 "Solderbridge" Solderbridge_Shorted 53.34,14.499 r90 top net-tie
SB7 "Solderbridge" Solderbridge_Shorted 68.58,48.999 r270 top net-tie
SB8 "Solderbridge" Solderbridge_Shorted 103.472,50.8 r0 top net-tie
SB9 "Solderbridge" Solderbridge_Shorted 55.88,14.499 r90 top net-tie
SB10 "Solderbridge" Solderbridge_Shorted 58.42,14.499 r90 top net-tie
SB11 "Solderbridge" Solderbridge 84,29.249 r0 top
SB12 "Solderbridge" Solderbridge 106,13.974 r180 top
SB13 "Solderbridge" Solderbridge 71.5,15.249 r180 top
SB14 "Solderbridge" Solderbridge_Shorted 71.5,13.249 r180 top net-tie
SB15 "Solderbridge" Solderbridge 9.75,57.249 r0 top
SB16 "Solderbridge" Solderbridge 9.75,59.094 r0 top
SB17 "Solderbridge" Solderbridge_Shorted 36.576,39.147 r90 top net-tie
SB18 "Solderbridge" Solderbridge_Shorted 67,27.749 r180 top net-tie
SB19 "Solderbridge" Solderbridge 67,26.249 r0 top
SB20 "Solderbridge" Solderbridge 73.66,42.204 r90 top
SB21 "Solderbridge" Solderbridge_Shorted 57.5,20.249 r270 top net-tie
SB22 "Solderbridge" Solderbridge 58.5,26.249 r270 top
SB23 "Solderbridge" Solderbridge_Shorted 57,26.249 r270 top net-tie
SB24 "Solderbridge" Solderbridge_Shorted 59,20.249 r270 top net-tie
SB25 "Solderbridge" Solderbridge_Shorted 56,31.98 r0 top net-tie
SB26 "Solderbridge" Solderbridge 56,30.48 r90 top
SB27 "Solderbridge" Solderbridge 56,24.249 r90 top
SB28 "Solderbridge" Solderbridge_Shorted 56,28.98 r0 top net-tie
SB29 "Solderbridge" Solderbridge 13.525,21.699 r270 top
SB30 "Solderbridge" Solderbridge_Shorted_Power 26.2,11.199 r90 top net-tie
SB31 "Solderbridge" Solderbridge_Shorted_Power 20.066,39.147 r180 top net-tie
SB32 "Solderbridge" Solderbridge_Shorted 24.6,12.399 r90 top net-tie
SB33 "Solderbridge" Solderbridge_Shorted_Power 24.6,11.199 r90 top net-tie
SB34 "Solderbridge" Solderbridge 15.24,47.318 r270 top
SB35 "Solderbridge" Solderbridge_Shorted_Power 4.1,10.799 r270 top net-tie
SW1 "PB SW" L-KLS7-TS6616B-2.5-160-T 117.64,12.999 r180 top
SW2 "PB SW" L-KLS7-TS6616B-2.5-160-T 128.29,12.999 r180 top
SW3 "PB SW" L-KLS7-TS6616B-2.5-160-T 117.64,3.999 r0 top
SW4 "PB SW" L-KLS7-TS6616B-2.5-160-T 128.29,3.999 r0 top
SW5 "PB SW" L-KLS7-TS6616B-2.5-160-T 21.136,3.999 r180 top
SW6 "Switch" JS102011JAQN 6.35,4.834 r0 top
TP1 "Ø1.0mm,SMD" TP_SMD_D1.0mm 129.5,32.099 r180 top
TP2 "Ø1.0mm,SMD" TP_SMD_D1.0mm 127.7,32.099 r180 top
TP3 "Ø1.5mm,SMD" TP_SMD_D1.5mm 33.02,19.049 r0 top
TP4 "Ø1.5mm,SMD" TP_SMD_D1.5mm 35.56,19.049 r0 top
TP5 "Ø1.5mm,SMD" TP_SMD_D1.5mm 33.02,16.509 r0 top
TP6 "Ø1.5mm,SMD" TP_SMD_D1.5mm 35.56,16.509 r0 top
TP7 "Ø1.5mm,SMD" TP_SMD_D1.5mm 43.18,19.049 r0 top
TP8 "Ø1.5mm,SMD" TP_SMD_D1.5mm 45.72,19.049 r0 top
TP9 "Ø1.5mm,SMD" TP_SMD_D1.5mm 43.18,16.509 r0 top
TP10 "Ø1.5mm,SMD" TP_SMD_D1.5mm 45.72,16.509 r0 top
TP11 "Ø1.5mm,SMD" TP_SMD_D1.5mm 23,21.749 r0 top
TP12 "Ø1.5mm,SMD" TP_SMD_D1.5mm 32.129,22.352 r90 bottom
TP13 "Ø1.5mm,SMD" TP_SMD_D1.5mm 36.957,24.765 r90 bottom
TP14 "Ø1.5mm,SMD" TP_SMD_D1.5mm 36.283,20.649 r90 bottom
TP15 "Ø1.5mm,SMD" TP_SMD_D1.5mm 36.83,29.528 r90 bottom
TP16 "Ø1.5mm,SMD" TP_SMD_D1.5mm 29.108,15.385 r90 bottom
TP17 "Ø1.5mm,SMD" TP_SMD_D1.5mm 6.248,36.323 r180 bottom
TP18 "Ø1.5mm,SMD" TP_SMD_D1.5mm 6.985,25.101 r180 bottom
TP19 "Ø1.5mm,SMD" TP_SMD_D1.5mm 11.074,33.275 r180 bottom
TP20 "Ø1.5mm,SMD" TP_SMD_D1.5mm 11.582,30.759 r180 bottom
TP21 "Ø1.5mm,SMD" TP_SMD_D1.5mm 19.85,10.249 r270 top
TP22 "Ø1.5mm,SMD" TP_SMD_D1.5mm 2.921,15.717 r90 bottom
TP23 "Ø1.5mm,SMD" TP_SMD_D1.5mm 24.795,21.379 r90 bottom
TP24 "TP" TESTPAD-TH 98,59.999 r0 top
TP25 "Ø1.5mm,SMD" TP_SMD_D1.5mm 8.3,13.699 r270 bottom
TP26 "Ø1.5mm,SMD" TP_SMD_D1.5mm 8.44,16.509 r270 bottom
TP27 "Ø1.5mm,SMD" TP_SMD_D1.5mm 6.604,9.398 r270 bottom
U1 "ECMF02-4CMX8" UFDFN50P120X250X55-8N 11.6,32.199 r0 top
U3 "nRF5340-QKAA" AQFN40P700X700X85_HS-99N 24.925,28.458 r0 top
U4 "GD25WB256E" SON127P800X80_HS-9N 79.187,38.399 r90 top
U5 "PCAL6408A" XQFN40P180X260X50-16N 103.41,32.349 r180 top
U6 "MFFx_M2M_UICC" SON127P600X90_HS-8N 76,14.249 r0 top value="M2M UICC"
U7_S1 "FSA2466UMX" XQFN40P180X260X50-16N 64.8,44.649 r270 top (schematic designator U7)
U7_S2 "FSA2466UMX" XQFN40P180X260X50-16N 51.4,18.499 r270 top (schematic designator U7)
U7_S3 "FSA2466UMX" XQFN40P180X260X50-16N 16.6,27.449 r180 top (schematic designator U7)
U7_S4 "FSA2466UMX" XQFN40P180X260X50-16N 29.9,38.049 r90 top (schematic designator U7)
U7_S5 "FSA2466UMX" XQFN40P180X260X50-16N 103.41,36.208 r0 top (schematic designator U7)
U7_S6 "FSA2466UMX" XQFN40P180X260X50-16N 103.41,27.483 r180 top (schematic designator U7)
U7_S8 "FSA2466UMX" XQFN40P180X260X50-16N 85.2,36.874 r180 top (schematic designator U7)
U7_S10 "FSA2466UMX" XQFN40P180X260X50-16N 58.5,23.249 r0 top (schematic designator U7)
U7_S11 "FSA2466UMX" XQFN40P180X260X50-16N 56.418,44.649 r270 top (schematic designator U7)
U8_S7 "NX3DV2567" XQFN40P180X260X50-16N 99,32.349 r180 top (schematic designator U8)
U8_S9 "NX3DV2567" XQFN40P180X260X50-16N 88.1,18.049 r0 top (schematic designator U8)
U9 "nPM1300-QEAA" Nordic_QFN50P500X500X90-33N 12.525,14.174 r180 top
X1 "32MHz" BT-XTAL_2016 32.05,32.312 r90 top
Y1 "Shunt 2.54mm" Shunt_2.54mm_Horizontal 3.485,49.858 r270 top
Y2 "Shunt 2.54mm" Shunt_2.54mm_Horizontal 103.41,3.493 r0 top

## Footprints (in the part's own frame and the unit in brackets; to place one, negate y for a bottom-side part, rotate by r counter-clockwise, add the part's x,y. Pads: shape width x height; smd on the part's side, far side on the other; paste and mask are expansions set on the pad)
AQFN40P700X700X85_HS-99N [mm] "AQFN, 98-Leads, Body 7.00x7.00mm, Pitch 0.40mm, Thermal Pad 5.4x5.0mm, IPC Medium Density"
  rect 5.4x5 smd paste-5 mask+0.05: 104(0.2,0)
  round 0.4 smd paste+0.012 mask+0.05: A1(-3.2,3.2) A31(3.2,3.2) AL1(-3.2,-3.2) AL31(3.2,-3.2)
  round 0.225 smd paste+0.012 mask+0.05: A5(-2.2,3.2) A13(-0.6,3.2) A15(-0.2,3.2) A17(0.2,3.2) A19(0.6,3.2) A21(1,3.2) A23(1.4,3.2) A25(1.8,3.2) A27(2.2,3.2) AA1(-3.2,-1) AA31(3.2,-1) AB2(-2.8,-1.2) AC1(-3.2,-1.4) AC31(3.2,-1.4) AD2(-2.8,-1.6) AE1(-3.2,-1.8) AE31(3.2,-1.8) AF2(-2.8,-2) AG1(-3.2,-2.2) AG31(3.2,-2.2) AH2(-2.8,-2.4) AJ1(-3.2,-2.6) AJ31(3.2,-2.6) AK2(-2.8,-2.8) AK4(-2.4,-2.8) AK6(-2,-2.8) AK8(-1.6,-2.8) AK10(-1.2,-2.8) AK12(-0.8,-2.8) AK14(-0.4,-2.8) AK16(0,-2.8) AK18(0.4,-2.8) AK20(0.8,-2.8) AK22(1.2,-2.8) AK24(1.6,-2.8) AK26(2,-2.8) AK28(2.4,-2.8) AK30(2.8,-2.8) AL3(-2.6,-3.2) AL5(-2.2,-3.2) AL7(-1.8,-3.2) AL9(-1.4,-3.2) AL11(-1,-3.2) AL13(-0.6,-3.2) AL15(-0.2,-3.2) AL17(0.2,-3.2) AL19(0.6,-3.2) AL21(1,-3.2) AL23(1.4,-3.2) AL25(1.8,-3.2) AL27(2.2,-3.2) AL29(2.6,-3.2) B2(-2.8,2.8) B4(-2.4,2.8) B6(-2,2.8) B8(-1.6,2.8) B10(-1.2,2.8) B12(-0.8,2.8) B14(-0.4,2.8) B16(0,2.8) B18(0.4,2.8) B20(0.8,2.8) B22(1.2,2.8) B24(1.6,2.8) B26(2,2.8) B28(2.4,2.8) B30(2.8,2.8) C1(-3.2,2.6) C31(3.2,2.6) D2(-2.8,2.4) E1(-3.2,2.2) E31(3.2,2.2) F2(-2.8,2) G1(-3.2,1.8) G31(3.2,1.8) H2(-2.8,1.6) J1(-3.2,1.4) J31(3.2,1.4) K2(-2.8,1.2) L1(-3.2,1) L31(3.2,1) M2(-2.8,0.8) N1(-3.2,0.6) N31(3.2,0.6) P2(-2.8,0.4) R1(-3.2,0.2) R31(3.2,0.2) T2(-2.8,0) U1(-3.2,-0.2) U31(3.2,-0.2) V2(-2.8,-0.4) W1(-3.2,-0.6) W31(3.2,-0.6) Y2(-2.8,-0.8)
  rrect15% 1.1x1 on Top Paste: ""(-1.75,-1.8) ""(-1.75,-0.6) ""(-1.75,0.6) ""(-1.75,1.8) ""(-0.45,-1.8) ""(-0.45,-0.6) ""(-0.45,0.6) ""(-0.45,1.8) ""(0.85,-1.8) ""(0.85,-0.6) ""(0.85,0.6) ""(0.85,1.8) ""(2.15,-1.8) ""(2.15,-0.6) ""(2.15,0.6) ""(2.15,1.8)
  silkscreen extent -4.22,3.23 -3.97,3.47, body extent -3.5,-3.5 3.5,3.5, height 0.85
BT-XTAL_2016 [mm] "Crystal 2.0 x 1.6 mm"
  rect 0.95x0.85 smd: 1(-0.725,-0.575) 2(0.725,-0.575) 3(0.725,0.575) 4(-0.725,0.575)
  body extent -1.05,-0.85 1.05,0.85, height 0.56
CAPC0603X03L_C [mm] "Chip Capacitor, 2-Leads, Body 0.6x0.3mm, IPC High Density"
  rect 0.27x0.3 smd mask+0.05: 1(-0.285,0) 2(0.285,0)
  body extent -0.3,-0.15 0.31,0.15, height 0.3
CAPC0603X03L_C_NC [mm] "Chip Capacitor, 2-Leads, Body 0.6x0.3mm, IPC High Density"
  rect 0.27x0.3 smd mask+0.05: 1(-0.285,0) 2(0.285,0)
CAPC1005X04L [mm] "Chip Capacitor, 2-Leads, Body 1.0x0.5mm, IPC High Density"
  rect 0.6x0.5 smd: 1(-0.5,0) 2(0.5,0)
  body extent -0.51,-0.25 0.51,0.25, height 0.5
CAPC1608X06L [mm] "Chip Capacitor, 2-Leads, Body 1.6x0.8mm, IPC High Density"
  rect 0.75x0.8 smd: 1(-0.675,0) 2(0.675,0)
  silkscreen extent -1.17,-0.5 1.17,0.5, body extent -0.8,-0.43 0.8,0.43, height 0.8
CAPC1608X06L_NC [mm] "Chip Capacitor, 2-Leads, Body 1.6x0.8mm, IPC High Density"
  rect 0.75x0.8 smd: 1(-0.675,0) 2(0.675,0)
  silkscreen extent -1.17,-0.5 1.17,0.5
CONSMA024-G [mm]
  rect 1x1.5 smd: 1(0,-4.9)
  rect 1.15x6.85 smd: 2(-4.175,-0.125) 2(4.175,-0.125)
  oval 0.7x7.2 hole 0.5 slot 7.1 at 90 deg: 2(-3.35,0) 2(3.35,0)
  Multi-Layer region: -3.498,-4.098 -3.498,3.3 -4.9,3.3 -4.9,-4.098
  Multi-Layer region: 4.9,-4.098 4.9,3.3 3.498,3.3 3.498,-4.098
  body extent -4.5,-5.5 4.5,9.5, height 4
DFN65P100X40-3L [mm] "DFN, 3-Leads, Body 0.60x1.00mm, Pitch 0.65mm, IPC High Density"
  rect 0.4x0.25 smd mask+0.05: 1(-0.35,0.225) 2(-0.35,-0.225)
  rect 0.4x0.7 smd mask+0.065: 3(0.35,0)
  body extent -0.53,-0.33 0.53,0.33, height 0.4
DFN65P200X200X80_HS-6N [mm] "DFN, 6-Leads, Body 2.00x2.00mm, Pitch 0.65mm, IPC Medium Density"
  rect 0.45x0.42 smd mask+0.055: 1(-0.905,0.65) 2(-0.905,0) 3(-0.905,-0.65) 4(0.905,-0.65) 5(0.905,0) 6(0.905,0.65)
  rect 0.92x0.71 smd mask+0.055: 3(0,-0.475) 6(0,0.475)
  body extent -1.05,-1.05 1.05,1.05, height 0.65
Fiducial [mm] "Fiducial Mark"
  round 1 smd far side paste+0 mask+0.5: 0(0,0)
  round 1 smd paste+0 mask+0.5: 0(0,0)
  Top Layer keep-out circle w0.01: c0,0 r1
  Bottom Layer keep-out circle w0.01: c0,0 r1
HDR_2x3-SMD [mil] "Board-Board Conn, Header, 6-way, 2-row"
  rect 40x113 smd: 1(-100,-100) 2(-100,100) 3(0,-100) 4(0,100) 5(100,-100) 6(100,100)
  silkscreen extent -160,-140 150,100, body extent -150,-148 150,148, height 382
HDR_2x5-SMD-1.27mm [mm] "Pin Header, 1.27mm SMD"
  rect 0.76x2.4 smd: 1(-2.54,-1.95) 2(-2.54,1.95) 3(-1.27,-1.95) 4(-1.27,1.95) 5(0,-1.95) 6(0,1.95) 7(1.27,-1.95) 8(1.27,1.95) 9(2.54,-1.95) 10(2.54,1.95)
  silkscreen extent -3.17,-0.35 3.17,0.35, body extent -3.16,-2.92 3.19,2.92, height 5.96
HDR_2x5-SMD-1.27mm-K [mm] "SMT MICRO HEADER, (1,27) .050\" Keying Shroud"
  rect 0.76x2.4 smd: 1(-2.54,-1.95) 2(-2.54,1.95) 3(-1.27,-1.95) 4(-1.27,1.95) 5(0,-1.95) 6(0,1.95) 7(1.27,-1.95) 8(1.27,1.95) 9(2.54,-1.95) 10(2.54,1.95)
  silkscreen extent -3.17,-0.35 3.17,0.35, body extent -3.14,-2.92 3.14,2.92, height 6.11
HDR_2x6-NC [mm] "Pin Header, 2.54mm through hole"
  rect 1.5x1.5 hole 0.9: 1(-6.35,-1.27)
  round 1.5 hole 0.9: 2(-6.35,1.27) 3(-3.81,-1.27) 4(-3.81,1.27) 5(-1.27,-1.27) 6(-1.27,1.27) 7(1.27,-1.27) 8(1.27,1.27) 9(3.81,-1.27) 10(3.81,1.27) 11(6.35,-1.27) 12(6.35,1.27)
  silkscreen extent -7.62,-2.41 7.62,2.54
HDR_2x8-NC [mm] "Pin Header, 2.54mm through hole"
  rect 1.5x1.5 hole 0.9: 1(-8.89,-1.27)
  round 1.5 hole 0.9: 2(-8.89,1.27) 3(-6.35,-1.27) 4(-6.35,1.27) 5(-3.81,-1.27) 6(-3.81,1.27) 7(-1.27,-1.27) 8(-1.27,1.27) 9(1.27,-1.27) 10(1.27,1.27) 11(3.81,-1.27) 12(3.81,1.27) 13(6.35,-1.27) 14(6.35,1.27) 15(8.89,-1.27) 16(8.89,1.27)
  silkscreen extent -10.16,-2.41 10.16,2.54
HDR_2x10-NC [mm] "Pin Header, 2.54mm through hole"
  rect 1.5x1.5 hole 0.9: 1(-11.43,-1.27)
  round 1.5 hole 0.9: 2(-11.43,1.27) 3(-8.89,-1.27) 4(-8.89,1.27) 5(-6.35,-1.27) 6(-6.35,1.27) 7(-3.81,-1.27) 8(-3.81,1.27) 9(-1.27,-1.27) 10(-1.27,1.27) 11(1.27,-1.27) 12(1.27,1.27) 13(3.81,-1.27) 14(3.81,1.27) 15(6.35,-1.27) 16(6.35,1.27) 17(8.89,-1.27) 18(8.89,1.27) 19(11.43,-1.27) 20(11.43,1.27)
  silkscreen extent -12.7,-2.41 12.7,2.54
HDR_2x10-SMD-1.27mm-K-SWD [mm] "SMT MICRO HEADER, (1,27) .050\" Keying Shroud w/ pin 7 removed"
  rect 0.76x2.4 smd: 1(-5.715,-1.95) 2(-5.715,1.95) 3(-4.445,-1.95) 4(-4.445,1.95) 5(-3.175,-1.95) 6(-3.175,1.95) 8(-1.905,1.95) 9(-0.635,-1.95) 10(-0.635,1.95) 11(0.635,-1.95) 12(0.635,1.95) 13(1.905,-1.95) 14(1.905,1.95) 15(3.175,-1.95) 16(3.175,1.95) 17(4.445,-1.95) 18(4.445,1.95) 19(5.715,-1.95) 20(5.715,1.95)
  silkscreen extent -6.35,-3.15 6.35,0.35, body extent -6.35,-2.92 6.35,2.92, height 6.11
INDC0603X03L_C [mm] "Chip Inductor, 2-Leads, Body 0.6x0.3mm, IPC High Density"
  rect 0.27x0.3 smd: 1(-0.285,0) 2(0.285,0)
  body extent -0.3,-0.15 0.3,0.15, height 0.3
INDC1005X04L_NC [mm] "Chip Inductor, 2-Leads, Body 1.0x0.5mm, IPC High Density"
  rect 0.65x0.5 smd: 1(-0.475,0) 2(0.475,0)
INDC1005X04L_WW [mm] "Chip Inductor, 2-Leads, Body 1.0x0.5mm, IPC High Density"
  rect 0.65x0.5 smd: 1(-0.475,0) 2(0.475,0)
  body extent -0.5,-0.3 0.5,0.3, height 0.51
INDC1608X06L [mm] "Chip Inductor, 2-Leads, Body 1.6x0.8mm, IPC High Density"
  rect 0.75x0.8 smd: 1(-0.675,0) 2(0.675,0)
  silkscreen extent -1.17,-0.5 1.17,0.5, body extent -0.8,-0.48 0.8,0.48, height 0.8
INDC2016X10N [mm] "Chip Inductor, 2-Leads, Body 2.00x1.60mm, IPC Medium Density"
  rect 1.13x1.82 smd: 1(-0.885,0) 2(0.885,0)
  body extent -1.1,-0.9 1.1,0.9, height 1
JS102011JAQN [mm] "Slide Switches - DPDT, SMD, ON-ON"
  round 0.9 hole 0.9 unplated mask+0: 0(-3.4,0) 0(3.4,0)
  rect 0.5x0.5 smd: 1(-2.5,-1.2) 3(2.5,-1.2) 4(-2.5,1.2) 6(2.5,1.2)
  rect 1x1.6 smd: 2(0,-1.2) 5(0,1.2)
  Top Layer region: -3,0.562 -2.838,0.4 -2,0.4 -2,2 -3,2
  Top Layer region: -3,-0.562 -2.838,-0.4 -2,-0.4 -2,-2 -3,-2
  Top Layer region: 3,0.562 2.838,0.4 2,0.4 2,2 3,2
  Top Layer region: 3,-0.562 2.838,-0.4 2,-0.4 2,-2 3,-2
  silkscreen extent -4.5,-3.8 4.5,1.75, body extent -4.25,-3.75 4.25,1.75, height 3.5
KLS1-SIM-066 [mm]
  rect 0.7x2.1 smd: 0(-1.67,-13.55) 0(-1.67,-1.55) 0(11.32,-13.55) 0(11.32,-1.55)
  rect 0.75x1.2 smd: C1(5.08,0) C2(2.54,0) C3(0,0) C5(6.35,0) C6(3.81,0) C7(1.27,0)
  rect 0.65x1.2 smd: CD(7.3,0)
  round 0.75 hole 0.75 unplated: ""(-0.17,-12.3) ""(8.33,-12.3)
  Top Layer keep-out region: 6.83,-13.4 5.63,-13.4 5.63,-9.6 6.83,-9.6
  Top Layer keep-out region: 4.29,-13.4 3.09,-13.4 3.09,-9.6 4.29,-9.6
  Top Layer keep-out region: 1.75,-13.4 0.55,-13.4 0.55,-9.6 1.75,-9.6
  Top Layer keep-out region: 6.83,-6.5 5.63,-6.5 5.63,-2.7 6.83,-2.7
  Top Layer keep-out region: 4.29,-6.5 3.09,-6.5 3.09,-2.7 4.29,-2.7
  Top Layer keep-out region: 1.75,-6.5 0.55,-6.5 0.55,-2.7 1.75,-2.7
  silkscreen extent -1.38,-14.3 11.02,-0.7, body extent -1.72,-14.49 11.37,0.09, height 1.44
L-KLS7-TS6616B-2.5-160-T [mm] "6.2Ã—6.4mm TACT Switch, without ground connector"
  rect 2.75x1.4 smd: 1(-3.025,2) 1(3.025,2) 2(-3.025,-2) 2(3.025,-2)
  silkscreen extent -3,-3 3,3, body extent -3.6,-3.1 3.6,3.1, height 2.5
LabelSilk_15x40 [mm] "PCA version label, stick-on, 15x40mm"
  silkscreen extent 0,0 40,15, body extent 0,0 40,15, height 0.05
LED_0603_G [mil] "SMD Super Bright LED, GREEN"
  rect 30x32 smd: 1(-27.5,0) 2(27.5,0)
  silkscreen extent -58,-10 -58,10, body extent -32,-16 32,16, height 24
LGA50P1210X1110X130-113N [mm]
  rect 0.7x0.45 smd paste-2539.97 mask-5: 1(-5,-5.625)
  rect 0.3x0.45 smd mask+0.05: 2(-4.25,-5.625) 3(-3.75,-5.625) 4(-3.25,-5.625) 5(-2.75,-5.625) 6(-2.25,-5.625) 7(-1.75,-5.625) 8(-1.25,-5.625) 9(-0.75,-5.625) 10(-0.25,-5.625) 11(0.25,-5.625) 12(0.75,-5.625) 13(1.25,-5.625) 14(1.75,-5.625) 15(2.25,-5.625) 16(2.75,-5.625) 17(3.25,-5.625) 18(3.75,-5.625) 19(4.25,-5.625) 42(4.25,5.625) 43(3.75,5.625) 44(3.25,5.625) 45(2.75,5.625) 46(2.25,5.625) 47(1.75,5.625) 48(1.25,5.625) 49(0.75,5.625) 50(0.25,5.625) 51(-0.25,5.625) 52(-0.75,5.625) 53(-1.25,5.625) 54(-1.75,5.625) 55(-2.25,5.625) 56(-2.75,5.625) 57(-3.25,5.625) 58(-3.75,5.625) 59(-4.25,5.625)
  rect 0.7x0.7 smd mask+0.05: 20(5,-5.5) 41(5,5.5) 60(-5,5.5)
  rect 0.45x0.3 smd mask+0.05: 21(5.125,-4.75) 22(5.125,-4.25) 23(5.125,-3.75) 24(5.125,-3.25) 25(5.125,-2.75) 26(5.125,-2.25) 27(5.125,-1.75) 28(5.125,-1.25) 29(5.125,-0.75) 30(5.125,-0.25) 31(5.125,0.25) 32(5.125,0.75) 33(5.125,1.25) 34(5.125,1.75) 35(5.125,2.25) 36(5.125,2.75) 37(5.125,3.25) 38(5.125,3.75) 39(5.125,4.25) 40(5.125,4.75) 61(-5.125,4.75) 62(-5.125,4.25) 63(-5.125,3.75) 64(-5.125,3.25) 65(-5.125,2.75) 66(-5.125,2.25) 67(-5.125,1.75) 68(-5.125,1.25) 69(-5.125,0.75) 70(-5.125,0.25) 71(-5.125,-0.25) 72(-5.125,-0.75) 73(-5.125,-1.25) 74(-5.125,-1.75) 75(-5.125,-2.25) 76(-5.125,-2.75) 77(-5.125,-3.25) 78(-5.125,-3.75) 79(-5.125,-4.25) 80(-5.125,-4.75)
  rect 0.3x0.3 smd mask+0.05: 81(-3.4,-4.1) 82(-2.85,-4.1) 83(-2.3,-4.1) 84(-0.55,-4.1) 85(0,-4.1) 86(0.55,-4.1) 87(2.3,-4.1) 88(2.85,-4.1) 89(3.4,-4.1) 90(2.15,-0.55) 91(2.15,0) 92(2.15,0.55) 93(3.4,4.1) 94(2.85,4.1) 95(2.3,4.1) 96(0.55,4.1) 97(0,4.1) 98(-0.55,4.1) 99(-2.3,4.1) 100(-2.85,4.1) 101(-3.4,4.1) 102(-2.15,0.55) 103(-2.15,0) 104(-2.15,-0.55)
  rect 1.6x1.6 smd mask+0.05: 105(-2.85,-2.85) 106(0,-2.85) 107(2.85,-2.85) 109(2.85,2.85) 110(0,2.85) 111(-2.85,2.85) 113(0,0)
  rect 1.95x1.6 smd mask+0.05: 108(3.575,0) 112(-3.575,0)
  Top Layer region: -5.35,-5.15 -5.35,-5.85 -4.65,-5.85 -4.65,-5.4 -4.9,-5.15
  silkscreen extent -5.99,-6.5 -5.69,-6.2, body extent -5.6,-6.1 5.6,6.1, height 1.21
LIST_1x6_SMD-NC [mm] "Pin List, 2.54mm, SMD"
  rect 1.02x2.19 smd: 1(0,-1.465) 1(0,1.465) 2(2.54,-1.465) 2(2.54,1.465) 3(5.08,-1.465) 3(5.08,1.465) 4(7.62,-1.465) 4(7.62,1.465) 5(10.16,-1.465) 5(10.16,1.465) 6(12.7,-1.465) 6(12.7,1.465)
  silkscreen extent -1.27,-1.27 13.97,1.27
LIST_1x8_SMD-NC [mm] "Pin List, 2.54mm, SMD"
  rect 1.02x2.19 smd: 1(0,-1.465) 1(0,1.465) 2(2.54,-1.465) 2(2.54,1.465) 3(5.08,-1.465) 3(5.08,1.465) 4(7.62,-1.465) 4(7.62,1.465) 5(10.16,-1.465) 5(10.16,1.465) 6(12.7,-1.465) 6(12.7,1.465) 7(15.24,-1.465) 7(15.24,1.465) 8(17.78,-1.465) 8(17.78,1.465)
  silkscreen extent -1.27,-1.27 19.05,1.27
LIST_1x10_SMD-NC [mm] "Pin List, 2.54mm, SMD"
  rect 1.02x2.19 smd: 1(0,-1.465) 1(0,1.465) 2(2.54,-1.465) 2(2.54,1.465) 3(5.08,-1.465) 3(5.08,1.465) 4(7.62,-1.465) 4(7.62,1.465) 5(10.16,-1.465) 5(10.16,1.465) 6(12.7,-1.465) 6(12.7,1.465) 7(15.24,-1.465) 7(15.24,1.465) 8(17.78,-1.465) 8(17.78,1.465) 9(20.32,-1.465) 9(20.32,1.465) 10(22.86,-1.465) 10(22.86,1.465)
  silkscreen extent -1.27,-1.27 24.13,1.27
LIST_1x13_SMD [mm] "Pin List, 2.54mm, SMD"
  rect 1.02x2.19 smd: 1(0,-1.465) 1(0,1.465) 2(2.54,-1.465) 2(2.54,1.465) 3(5.08,-1.465) 3(5.08,1.465) 4(7.62,-1.465) 4(7.62,1.465) 5(10.16,-1.465) 5(10.16,1.465) 6(12.7,-1.465) 6(12.7,1.465) 7(15.24,-1.465) 7(15.24,1.465) 8(17.78,-1.465) 8(17.78,1.465) 9(20.32,-1.465) 9(20.32,1.465) 10(22.86,-1.465) 10(22.86,1.465) 11(25.4,-1.465) 11(25.4,1.465) 12(27.94,-1.465) 12(27.94,1.465) 13(30.48,-1.465) 13(30.48,1.465)
  silkscreen extent -1.27,-1.27 31.75,1.27, body extent -1.27,-2.5 31.75,2.5, height 9.82
LIST_1x13_SMD-NC [mm] "Pin List, 2.54mm, SMD"
  rect 1.02x2.19 smd: 1(0,-1.465) 1(0,1.465) 2(2.54,-1.465) 2(2.54,1.465) 3(5.08,-1.465) 3(5.08,1.465) 4(7.62,-1.465) 4(7.62,1.465) 5(10.16,-1.465) 5(10.16,1.465) 6(12.7,-1.465) 6(12.7,1.465) 7(15.24,-1.465) 7(15.24,1.465) 8(17.78,-1.465) 8(17.78,1.465) 9(20.32,-1.465) 9(20.32,1.465) 10(22.86,-1.465) 10(22.86,1.465) 11(25.4,-1.465) 11(25.4,1.465) 12(27.94,-1.465) 12(27.94,1.465) 13(30.48,-1.465) 13(30.48,1.465)
  silkscreen extent -1.27,-1.27 31.75,1.27
LIST_ANG_1x2-SMD-2.54MM [mm] "Pin List, 2.54mm, Surface Mount, Angled"
  round 1.78 hole 1.78 unplated: 0(0,-4.496)
  rect 1.27x3.18 smd: 1(-1.27,0) 2(1.27,0)
  silkscreen extent -2.54,-11.58 2.54,-1.92, body extent -2.56,-11.61 2.52,1.35, height 3.03
LIST_ANG_1x4-SMD-2.54MM [mm] "Pin List, 2.54mm, Surface Mount, Angled"
  round 1.78 hole 1.78 unplated: 0(-2.54,-4.496) 0(2.54,-4.496)
  rect 1.27x3.18 smd: 1(-3.81,0) 2(-1.27,0) 3(1.27,0) 4(3.81,0)
  silkscreen extent -5.08,-11.58 5.08,-1.92, body extent -5.1,-11.61 5.06,1.35, height 3.03
LIST_ANG_1x6-SMD-2.54MM [mm] "Pin List, 2.54mm, Surface Mount, Angled"
  round 1.78 hole 1.78 unplated: 0(-5.08,-4.496) 0(5.08,-4.496)
  rect 1.27x3.18 smd: 1(-6.35,0) 2(-3.81,0) 3(-1.27,0) 4(1.27,0) 5(3.81,0) 6(6.35,0)
  silkscreen extent -6.6,-9.74 1.65,2.79, body extent -7.64,-11.61 7.6,1.35, height 3.03
Molex_502774-0891 [mm] "SD Micro, Molex 0473521001, Push-Push"
  rect 1.5x1.7 smd mask+0.05: 0(-0.75,14.77) 0(12.75,14.77)
  rect 1.6x1.5 smd mask+0.05: 0(-0.21,0)
  rect 1.7x1.5 smd mask+0.05: 0(12.45,0)
  rect 0.8x1.68 smd mask+0.05: 1(8.9,0.08) 2(7.8,0.08) 3(6.7,0.08) 4(5.6,0.08) 5(4.5,0.08) 6(3.4,0.08) 7(2.3,0.08) 8(1.2,0.08)
  rect 1.29x1.3 smd mask+0.05: 9(-0.96,1.6)
  rect 1.29x1.4 smd mask+0.05: 10(-0.96,8.97)
  silkscreen extent -1.2,0 13,15, body extent -1.2,-0.61 13.1,15.39, height 1.78
NORDIC_LOGO_LYING [mm]
  silkscreen extent -2.57,-2.24 13.7,2.24
Nordic_QFN50P500X500X90-33N [mm] "QFN32 5x5x0.85mm, 0.5mm pitch - Medium Density"
  oval 0.85x0.3 smd: 1(-2.45,1.75) 2(-2.45,1.25) 3(-2.45,0.75) 4(-2.45,0.25) 5(-2.45,-0.25) 6(-2.45,-0.75) 7(-2.45,-1.25) 8(-2.45,-1.75) 17(2.45,-1.75) 18(2.45,-1.25) 19(2.45,-0.75) 20(2.45,-0.25) 21(2.45,0.25) 22(2.45,0.75) 23(2.45,1.25) 24(2.45,1.75)
  oval 0.3x0.85 smd: 9(-1.75,-2.45) 10(-1.25,-2.45) 11(-0.75,-2.45) 12(-0.25,-2.45) 13(0.25,-2.45) 14(0.75,-2.45) 15(1.25,-2.45) 16(1.75,-2.45) 25(1.75,2.45) 26(1.25,2.45) 27(0.75,2.45) 28(0.25,2.45) 29(-0.25,2.45) 30(-0.75,2.45) 31(-1.25,2.45) 32(-1.75,2.45)
  rect 3.5x3.5 smd: 33(0,0)
  silkscreen extent -3.43,2.38 -3.18,2.62, body extent -2.5,-2.5 2.5,2.5, height 0.9
RESC0603X03L_C [mm] "Chip Resistor, 2-Leads, Body 0.6x0.3mm, IPC High Density"
  rect 0.27x0.3 smd: 1(-0.285,0) 2(0.285,0)
  body extent -0.3,-0.15 0.3,0.15, height 0.23
RESC0603X03L_C_NC [mm] "Chip Resistor, 2-Leads, Body 0.6x0.3mm, IPC High Density"
  rect 0.27x0.3 smd: 1(-0.285,0) 2(0.285,0)
RESC1005X04L_NC [mm] "Chip Resistor, 2-Leads, Body 1.0x0.5mm, IPC High Density"
  rect 0.6x0.55 smd mask+0.05: 1(-0.5,0) 2(0.5,0)
RESC2012X11L [mm] "Chip Resistor, 2-Leads, Body 2.0x1.3mm, IPC High Density"
  rect 1.15x1.35 smd: 1(-0.775,0) 2(0.775,0)
  silkscreen extent -1.45,-0.77 1.45,0.77, body extent -1,-0.62 1,0.63, height 0.5
SD-80259-001 [mm] "USB TYPE C RECEPTACLE, 16 PIN"
  round 0.6 hole 0.6 unplated: 0(-2.89,1.315) 0(2.89,1.315)
  rect 0.6x1.14 smd: A1(-3.2,2.385) A4(-2.4,2.385) A9(2.4,2.385) A12(3.2,2.385)
  rect 0.3x1.14 smd: A5(-1.25,2.385) A6(-0.25,2.385) A7(0.25,2.385) A8(1.25,2.385) B5(1.75,2.385) B6(0.75,2.385) B7(-0.75,2.385) B8(-1.75,2.385)
  oval 0.9x2 hole 0.6 slot 1.7 at 90 deg: SHLD(-4.325,1.795) SHLD(4.325,1.795)
  oval 0.9x1.7 hole 0.6 slot 1.4 at 90 deg: SHLD(-4.325,-2.385) SHLD(4.325,-2.385)
  oval 0.9x2 on Top Paste: ""(-4.32,1.795) ""(4.32,1.795)
  oval 0.9x1.7 on Top Paste: ""(-4.32,-2.385) ""(4.32,-2.385)
  silkscreen extent -4.33,-4.48 4.33,0.47, body extent -4.48,-4.98 4.48,2.74, height 3.26
SEGGER_LOGO_S [mm] "Logo 7.82 mm x 3.84 mm, print overlay"
  silkscreen extent -3.91,-1.92 3.91,1.92
Shunt_2.54mm_Horizontal [mm]
  body extent 0,-2.54 5.03,2.54, height 2.99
